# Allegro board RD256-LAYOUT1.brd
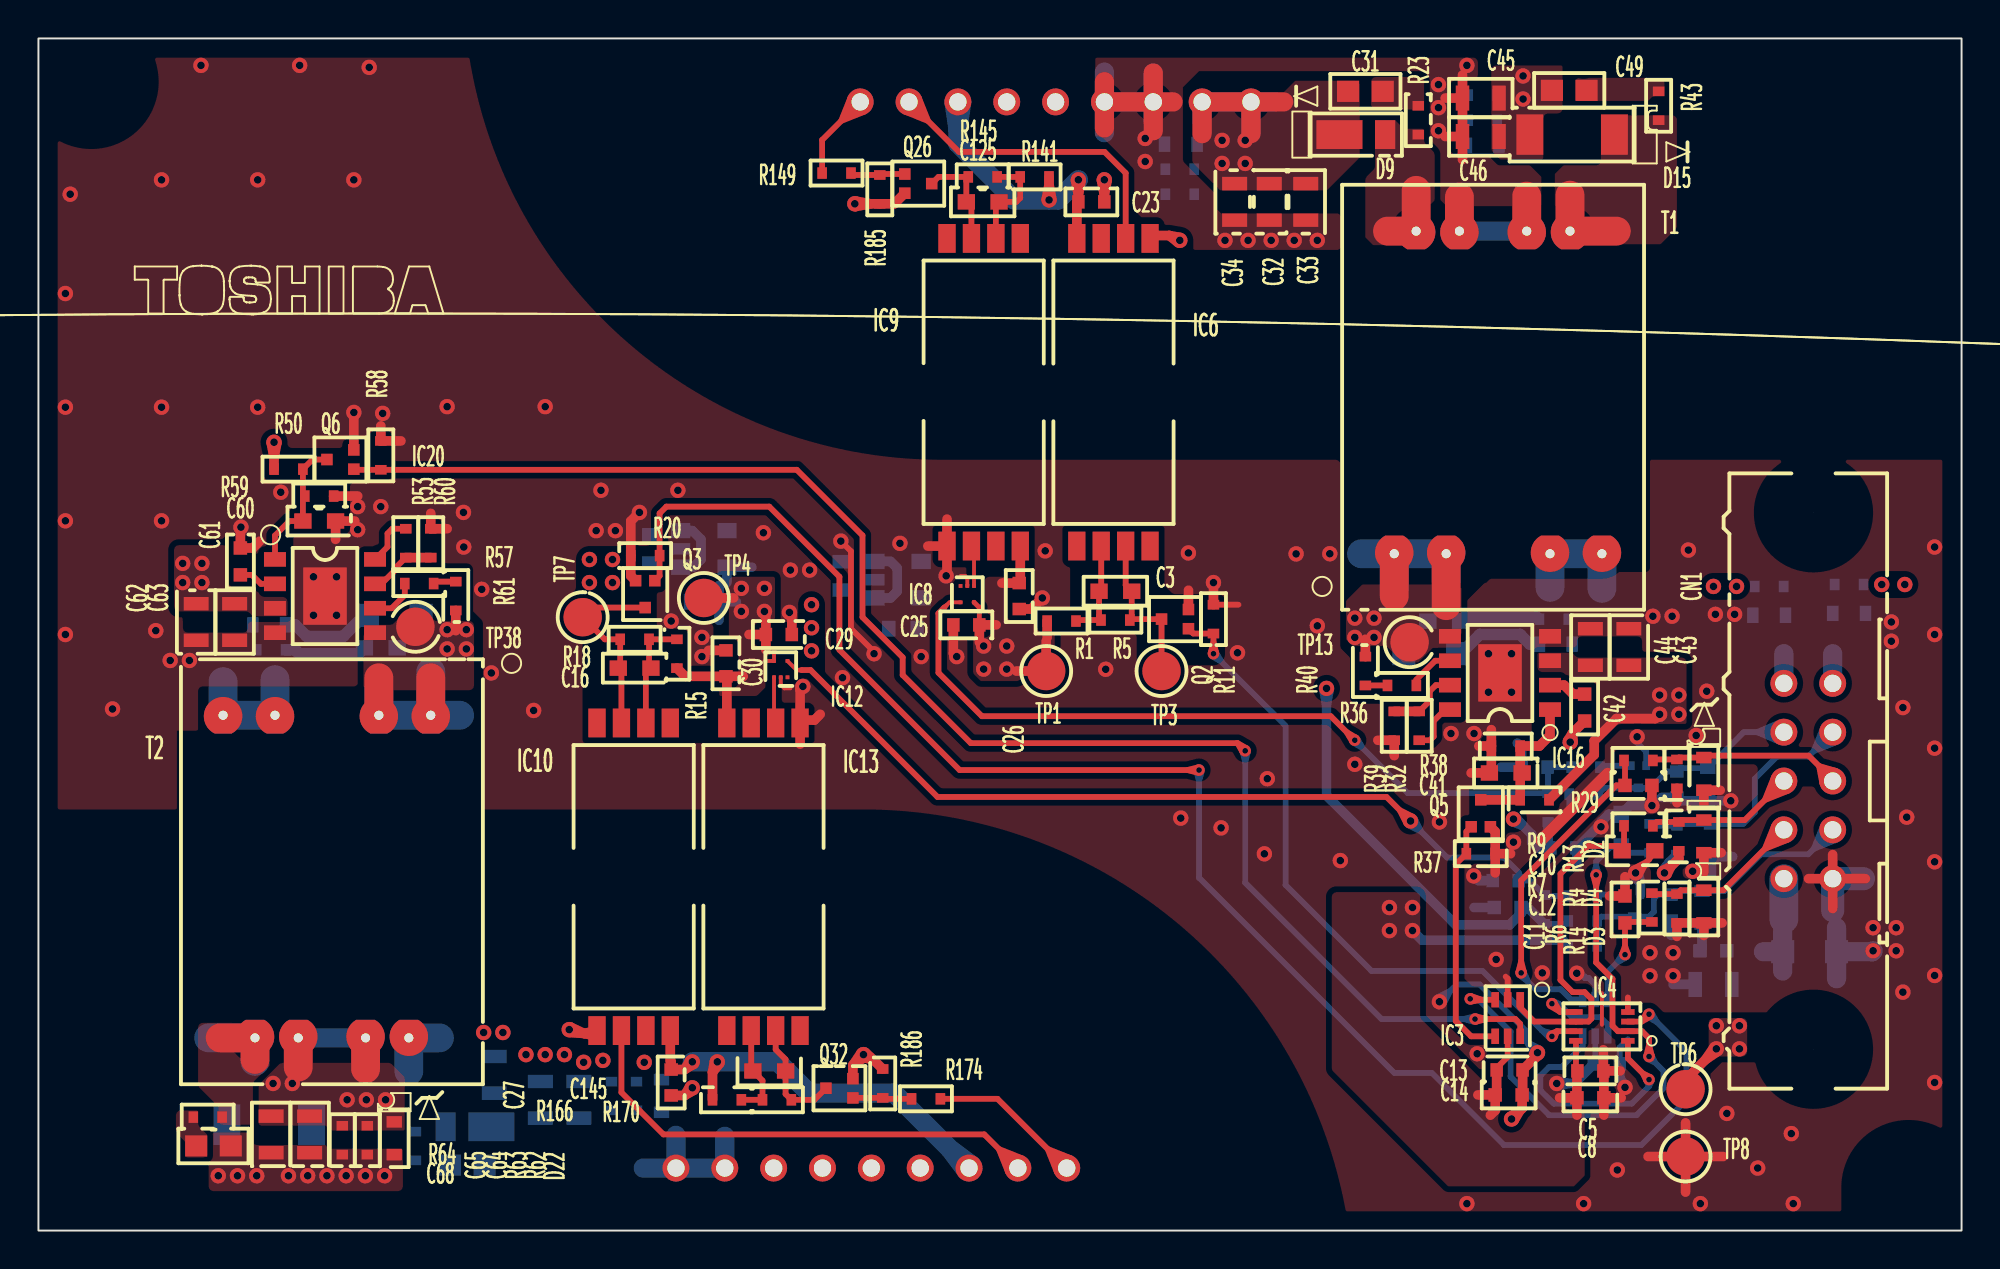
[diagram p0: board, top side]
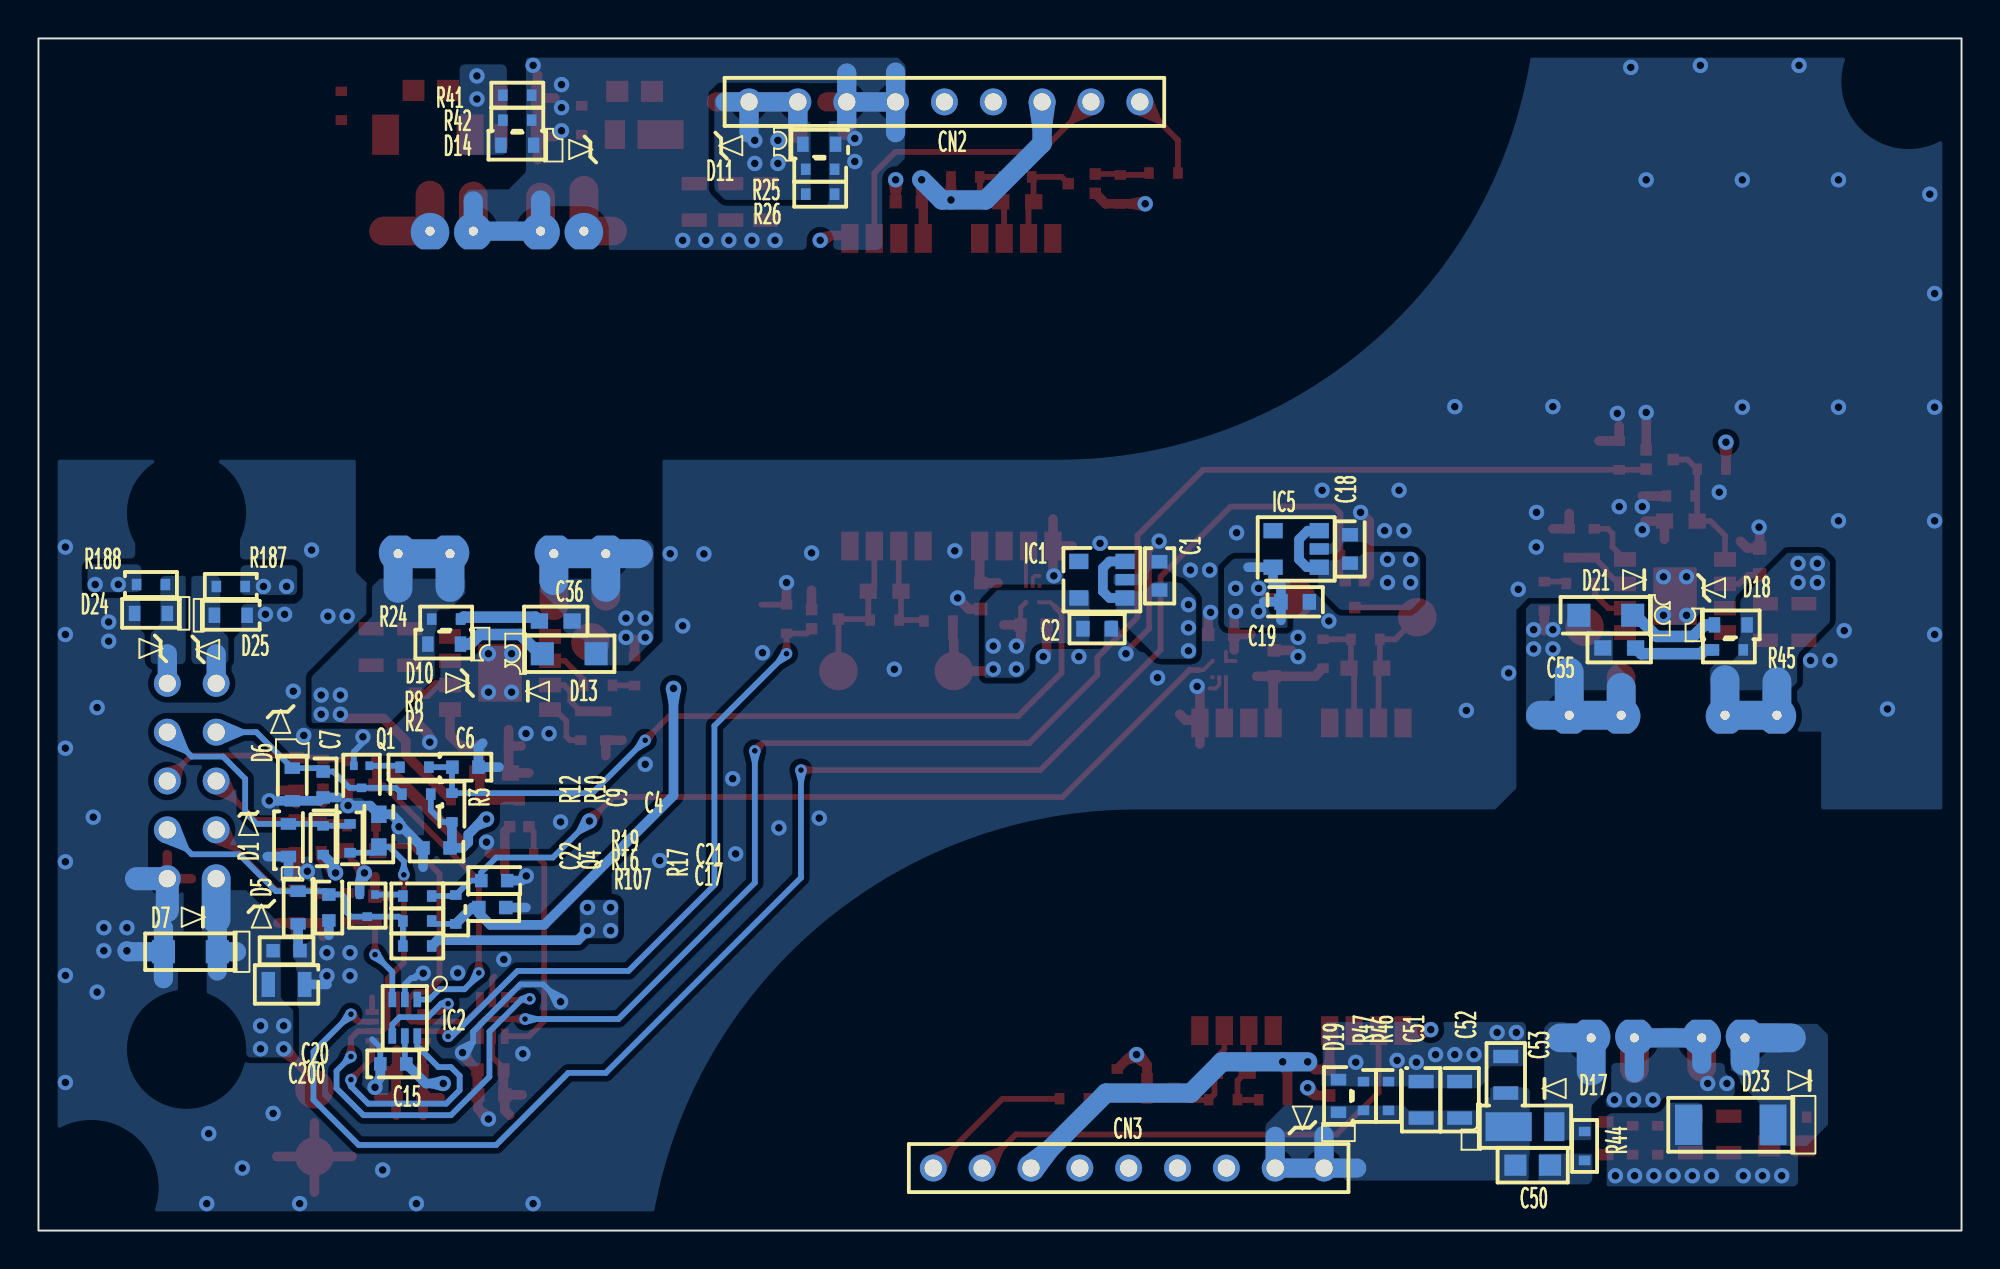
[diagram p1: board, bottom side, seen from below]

Outline 100 x 62 mm; copper layers: TOP, CONDUCTIVE2, CONDUCTIVE3, BOTTOM. Coordinates in mm from the lower left corner of the outline.
Outline path: rectangle 0,0 100,62

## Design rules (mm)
constraint set DEFAULT: 

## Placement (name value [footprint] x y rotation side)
C1  -  [C_CHP_TYYDN_L1_6W0_8H0_8A]  41.7 34.05 270 bottom
C2  -  [C_CHP_TYYDN_L1_6W0_8H0_8A]  44.95 31.3 0 bottom
C3  -  [C_CHP_YAGEO_L1_6W0_8H0_8]  56 33.25 180 top
C4  -  [C_CHP_TDK_L1_6W0_8H0_8]  79.3 19.9 180 bottom
C5  -  [C_CHP_MURATA_L1_6W0_8H0_8A]  80.7 8.3 180 top
C6  -  [C_CHP_MURATA_L1_6W0_8H0_8A]  77.8 24.1 0 bottom
C7  -  [C_CHP_MURATA_L1_6W0_8H0_8A]  85.2 23.2 90 bottom
C8  -  [C_CHP_TDK_L1_6W0_8H0_8]  80.7 6.9 180 top
C9  -  [C_CHP_YAGEO_L1_6W0_8H0_8]  82.3 20.8 270 bottom
C10  -  [C_CHP_TDK_L1_6W0_8H0_8]  83.2 23.15 180 top
C11  -  [C_CHP_TDK_L1_6W0_8H0_8]  82.5 16.7 270 top
C12  -  [C_CHP_YAGEO_L1_6W0_8H0_8]  83.2 19.75 180 top
C13  -  [C_CHP_MURATA_L1_6W0_8H0_8A]  76.5 8.35 180 top
C14  -  [C_CHP_TDK_L1_6W0_8H0_8]  76.45 7.05 180 top
C15  -  [C_CHP_MURATA_L1_6W0_8H0_8A]  81.55 8.67 180 bottom
C16  -  [C_CHP_YAGEO_L1_6W0_8H0_8]  31 29.25 0 top
C17  -  [C_CHP_TDK_L1_6W0_8H0_8]  76.4 16.8 0 bottom
C18  -  [C_CHP_TYYDN_L1_6W0_8H0_8A]  31.8 35.45 270 bottom
C19  -  [C_CHP_TYYDN_L1_6W0_8H0_8A]  34.65 32.7 0 bottom
C20  -  [C_CHP_TDK_L1_6W0_8H0_8]  87.1 14.55 0 bottom
C21  -  [C_CHP_MURATA_L1_6W0_8H0_8A]  76.3 18.2 0 bottom
C22  -  [C_CHP_MURATA_L1_6W0_8H0_8A]  84.9 16.8 90 bottom
C23  -  [C_CHP_MURATA_L1_6W0_8H0_8A]  54.75 53.5 180 top
C25  -  [C_CHP_MURATA_L1_6W0_8H0_8A]  48.25 31.5 0 top
C26  -  [C_CHP_MURATA_L1_6W0_8H0_8A]  51 33 90 top
C27  -  [C_CHP_MURATA_L1_6W0_8H0_8A]  32.9 7.7 90 top
C29  -  [C_CHP_MURATA_L1_6W0_8H0_8A]  38.5 31 180 top
C30  -  [C_CHP_MURATA_L1_6W0_8H0_8A]  35.75 29.5 270 top
C31  -  [C_CHP_KEMET_L1_6W0_8H0_8]  69 59.25 0 top
C32  -  [C_CHP_MURATA_L2_0W1_25H1_25]  64 53.5 90 top
C33  -  [C_CHP_MURATA_L2_0W1_25H1_25]  65.9 53.5 90 top
C34  -  [C_CHP_MURATA_L2_0W1_25H1_25]  62.2 53.5 90 top
C36  -  [C_CHP_YAGEO_L1_6W0_8H0_8]  73.1 31.7 0 bottom
C41  -  [C_CHP_YAGEO_L1_6W0_8H0_8]  76.3 23.8 0 top
C42  -  [C_CHP_TDK_L1_6W0_8H0_8]  80.4 27.2 90 top
C43  -  [C_CHP_MURATA_L2_0W1_25H1_25]  82.7 30.35 270 top
C44  -  [C_CHP_MURATA_L2_0W1_25H1_25]  80.7 30.35 270 top
C45  -  [C_CHP_MURATA_L2_0W1_25H1_25]  75 58.9 180 top
C46  -  [C_CHP_MURATA_L2_0W1_25H1_25]  75 56.9 180 top
C49  -  [C_CHP_KEMET_L1_6W0_8H0_8]  79.6 59.3 0 top
C50  -  [C_CHP_KEMET_L1_6W0_8H0_8]  22.3 3.4 180 bottom
C51  -  [C_CHP_MURATA_L2_0W1_25H1_25]  28.1 6.8 270 bottom
C52  -  [C_CHP_MURATA_L2_0W1_25H1_25]  26.1 6.8 270 bottom
C53  -  [C_CHP_MURATA_L2_0W1_25H1_25]  23.7 8.1 270 bottom
C55  -  [C_CHP_YAGEO_L1_6W0_8H0_8]  17.8 30.3 180 bottom
C60  -  [C_CHP_YAGEO_L1_6W0_8H0_8]  14.6 36.9 180 top
C61  -  [C_CHP_TDK_L1_6W0_8H0_8]  10.5 34.8 270 top
C62  -  [C_CHP_MURATA_L2_0W1_25H1_25]  8.2 31.65 90 top
C63  -  [C_CHP_MURATA_L2_0W1_25H1_25]  10.2 31.65 90 top
C64  -  [C_CHP_MURATA_L2_0W1_25H1_25]  14.1 5 90 top
C65  -  [C_CHP_MURATA_L2_0W1_25H1_25]  12.1 5 90 top
C68  -  [C_CHP_KEMET_L1_6W0_8H0_8]  9.1 4.4 180 top
C125  -  [C_CHP_YAGEO_L1_6W0_8H0_8]  49.1 53.5 0 top
C145  -  [C_CHP_YAGEO_L1_6W0_8H0_8]  38 8.3 180 top
C200  -  [C_CHP_MURATA_L2_0W1_25H1_25]  87.1 12.8 0 bottom
CN1  -  [CN_IMD_OMRON_XG4A_1031_M1_M2]  93.3 18.3 90 top
CN2  -  [OW_3_15_9P]  63.05 58.7 180 bottom
CN3  -  [OW_3_15_9P]  33.15 3.25 0 bottom
D1  -  [ZD_SMD_TSB_K_1_A_2_L1_2W0_8H0_6]  87 20.3 270 bottom
D2  -  [ZD_SMD_TSB_K_1_A_2_L1_2W0_8H0_6]  86.6 23.75 270 top
D3  -  [ZD_SMD_TSB_K_1_A_2_L1_2W0_8H0_6]  86.6 16.85 270 top
D4  -  [ZD_SMD_TSB_K_1_A_2_L1_2W0_8H0_6]  86.6 20.5 270 top
D5  -  [ZD_SMD_TSB_K_1_A_2_L1_2W0_8H0_6]  86.5 16.8 270 bottom
D6  -  [ZD_SMD_TSB_K_1_A_2_L1_2W0_8H0_6]  86.8 23.2 270 bottom
D7  -  [D_SMD_TSB_K_2_A_1_L2_6W1_6H0_98]  92.1 14.5 0 bottom
D9  -  [D_SMD_DIODES_K_C_A_A_L2_8W1_78H0_98]  68.5 57 0 top
D10  -  [ZD_SMD_TSB_K_1_A_2_L1_2W0_8H0_6]  78.9 30.5 0 bottom
D11  -  [ZD_SMD_TSB_K_1_A_2_L1_2W0_8H0_6]  59.4 56.5 180 bottom
D13  -  [D_SMD_TSB_K_2_A_1_L2_6W1_6H0_98]  72.4 30 180 bottom
D14  -  [ZD_SMD_TSB_K_1_A_2_L1_2W0_8H0_6]  75.1 56.45 0 bottom
D15  -  [D_SMD_TSB_K_2_A_1_L3_8W2_4H0_98]  79.75 57 180 top
D17  -  [D_SMD_DIODES_K_C_A_A_L2_8W1_78H0_98]  22.7 5.4 180 bottom
D18  -  [ZD_SMD_TSB_K_1_A_2_L1_2W0_8H0_6]  12 31.5 180 bottom
D19  -  [ZD_SMD_TSB_K_1_A_2_L1_2W0_8H0_6]  32.4 7 90 bottom
D21  -  [D_SMD_TSB_K_2_A_1_L2_6W1_6H0_98]  18.5 32 0 bottom
D22  -  [ZD_SMD_TSB_K_1_A_2_L1_2W0_8H0_6]  18.5 4.8 270 top
D23  -  [D_SMD_TSB_K_2_A_1_L3_8W2_4H0_98]  12 5.5 0 bottom
D24  -  [ZD_SMD_TSB_K_1_A_2_L1_2W0_8H0_6]  94.15 32.1 0 bottom
D25  -  [ZD_SMD_TSB_K_1_A_2_L1_2W0_8H0_6]  90 32 180 bottom
IC1  -  [IC_SC74A_TSB_L2_9W1_6H1_15_RP0_05]  44.7 33.85 90 bottom
IC2  -  [IC_SOP_6_TSB_L2_0W1_25H0_95_RP0_05]  80.95 11.07 0 bottom
IC3  -  [IC_SOP_6_TSB_L2_0W1_25H0_95_RP0_05]  76.4 11.05 180 top
IC4  -  [IC_SOP_8_TSB_L2_0W2_3H0_75_P0_5_RP0_05]  81.3 10.62 90 top
IC5  -  [IC_SC74A_TSB_L2_9W1_6H1_15_RP0_05]  34.6 35.45 90 bottom
IC6  -  [PC_SOP_8_TSB_L6_25W13_75H3_7_P1_27_3]  55.9 43.6 0 top
IC8  -  [IC_SMD_5_TSB_L1_0W0_8H0_48_RCNT]  48.3 33.1 180 top
IC9  -  [PC_SOP_8_TSB_L6_25W13_75H3_7_P1_27_3]  49.15 43.6 180 top
IC10  -  [PC_SOP_8_TSB_L6_25W13_75H3_7_P1_27_3]  30.95 18.4 180 top
IC12  -  [IC_SMD_5_TSB_L1_0W0_8H0_48_RCNT]  38.6 29.2 0 top
IC13  -  [PC_SOP_8_TSB_L6_25W13_75H3_7_P1_27_3]  37.7 18.4 0 top
IC16  -  [IC_SOP_8S1_AD_L5_004W3_988H1_752_P1_27_2]  76 29 90 top
IC20  -  [IC_SOP_8S1_AD_L5_004W3_988H1_752_P1_27_2]  14.9 33 270 top
NOREF  -  []  5 47.7 0 top
Q1  -  [TR_SMD_3_TSB_B_1_E_2_C_3_L1_2W0_8H0_5]  83.2 23.6 0 bottom
Q2  -  [FET_SMD_TSB_G_1_S_2_D_3_L1_6W0_8H0_75]  59.1 31.8 90 top
Q3  -  [FET_SMD_TSB_G_1_S_2_D_3_L1_6W0_8H0_75]  31.55 33.1 180 top
Q4  -  [TR_SMD_3_TSB_B_1_E_2_C_3_L1_2W0_8H0_5]  82.9 16.9 0 bottom
Q5  -  [FET_SMD_TSB_G_1_S_2_D_3_L1_6W0_8H0_75]  75 21.7 0 top
Q6  -  [FET_SMD_TSB_G_1_S_2_D_3_L1_6W0_8H0_75]  15.7 40.1 90 top
Q26  -  [FET_SMD_TSB_G_1_S_2_D_3_L1_6W0_8H0_75]  45.75 54.45 270 top
Q32  -  [FET_SMD_TSB_G_1_S_2_D_3_L1_6W0_8H0_75]  41.65 7.4 90 top
R1  -  [R_CHP_KOA_L1_6W0_8H0_45]  53.2 31.7 180 top
R2  -  [R_CHP_KOA_L1_6W0_8H0_45]  80.35 22.7 180 bottom
R3  -  [R_CHP_KOA_L1_6W0_8H0_45]  78.5 22 270 bottom
R4  -  [R_CHP_KOA_L1_6W0_8H0_45]  85.3 20.5 270 top
R5  -  [R_CHP_KOA_L1_6W0_8H0_45]  56 31.75 180 top
R6  -  [R_CHP_KOA_L1_6W0_8H0_45]  83.9 16.8 270 top
R7  -  [R_CHP_KOA_L1_6W0_8H0_45]  83.2 21.05 180 top
R8  -  [R_CHP_KOA_L1_6W0_8H0_45]  80.45 24.1 180 bottom
R9  -  [R_CHP_KOA_L1_6W0_8H0_45]  83.2 24.45 180 top
R10  -  [R_CHP_KOA_L1_6W0_8H0_45]  83.8 20.4 270 bottom
R11  -  [R_CHP_KOA_L1_6W0_8H0_45]  61.1 31.8 270 top
R12  -  [R_CHP_KOA_L1_6W0_8H0_45]  85.2 20.3 270 bottom
R13  -  [R_CHP_KOA_L1_6W0_8H0_45]  85.2 23.75 90 top
R14  -  [R_CHP_KOA_L1_6W0_8H0_45]  85.2 16.75 90 top
R15  -  [R_CHP_KOA_L1_6W0_8H0_45]  33.2 30 270 top
R16  -  [R_CHP_KOA_L1_6W0_8H0_45]  80.3 16.1 180 bottom
R17  -  [R_CHP_KOA_L1_6W0_8H0_45]  78.3 16.7 270 bottom
R18  -  [R_CHP_KOA_L1_6W0_8H0_45]  31 30.75 0 top
R19  -  [R_CHP_KOA_L1_6W0_8H0_45]  80.3 17.4 180 bottom
R20  -  [R_CHP_KOA_L1_6W0_8H0_45]  31.55 35.1 0 top
R23  -  [R_CHP_KOA_L1_6W0_8H0_45]  71.75 57.75 270 top
R24  -  [R_CHP_KOA_L1_6W0_8H0_45]  78.8 31.8 0 bottom
R25  -  [R_CHP_KOA_L1_6W0_8H0_45]  59.35 55.2 0 bottom
R26  -  [R_CHP_KOA_L1_6W0_8H0_45]  59.35 53.9 0 bottom
R29  -  [R_CHP_KOA_L1_6W0_8H0_45]  77.8 22.4 0 top
R32  -  [R_CHP_KOA_L1_6W0_8H0_45]  71.8 26.25 270 top
R36  -  [R_CHP_KOA_L1_6W0_8H0_45]  70.9 28.35 0 top
R37  -  [R_CHP_KOA_L1_6W0_8H0_45]  75 19.6 180 top
R38  -  [R_CHP_KOA_L1_6W0_8H0_45]  76.3 25.2 0 top
R39  -  [R_CHP_KOA_L1_6W0_8H0_45]  70.5 26.25 90 top
R40  -  [R_CHP_KOA_L1_6W0_8H0_45]  69 29.1 270 top
R41  -  [R_CHP_KOA_L1_6W0_8H0_45]  75.1 59.05 180 bottom
R42  -  [R_CHP_KOA_L1_6W0_8H0_45]  75.1 57.75 180 bottom
R43  -  [R_CHP_KOA_L1_6W0_8H0_45]  84.25 58.5 270 top
R44  -  [R_CHP_KOA_L1_6W0_8H0_45]  19.6 4.4 90 bottom
R45  -  [R_CHP_KOA_L1_6W0_8H0_45]  12.1 30.2 180 bottom
R46  -  [R_CHP_KOA_L1_6W0_8H0_45]  29.8 7 270 bottom
R47  -  [R_CHP_KOA_L1_6W0_8H0_45]  31.1 7 270 bottom
R50  -  [R_CHP_KOA_L1_6W0_8H0_45]  13 39.6 180 top
R53  -  [R_CHP_KOA_L1_6W0_8H0_45]  19.1 35.75 90 top
R57  -  [R_CHP_KOA_L1_6W0_8H0_45]  19.8 33.65 180 top
R58  -  [R_CHP_KOA_L1_6W0_8H0_45]  17.8 40.32 270 top
R59  -  [R_CHP_KOA_L1_6W0_8H0_45]  14.6 38.2 180 top
R60  -  [R_CHP_KOA_L1_6W0_8H0_45]  20.4 35.75 270 top
R61  -  [R_CHP_KOA_L1_6W0_8H0_45]  21.7 33 90 top
R62  -  [R_CHP_KOA_L1_6W0_8H0_45]  17.1 4.7 90 top
R63  -  [R_CHP_KOA_L1_6W0_8H0_45]  15.8 4.7 90 top
R64  -  [R_CHP_KOA_L1_6W0_8H0_45]  8.8 5.9 0 top
R107  -  [R_CHP_KOA_L1_6W0_8H0_45]  80.3 14.8 180 bottom
R141  -  [R_CHP_KOA_L1_6W0_8H0_45]  51.8 54.8 0 top
R145  -  [R_CHP_KOA_L1_6W0_8H0_45]  49.1 54.8 0 top
R149  -  [R_CHP_KOA_L1_6W0_8H0_45]  41.5 55 0 top
R166  -  [R_CHP_KOA_L1_6W0_8H0_45]  35.8 6.8 180 top
R170  -  [R_CHP_KOA_L1_6W0_8H0_45]  38.4 6.8 180 top
R174  -  [R_CHP_KOA_L1_6W0_8H0_45]  46.15 6.85 180 top
R185  -  [R_CHP_KOA_L1_6W0_8H0_45]  43.75 54.15 90 top
R186  -  [R_CHP_KOA_L1_6W0_8H0_45]  43.9 7.65 270 top
R187  -  [R_CHP_KOA_L1_6W0_8H0_45]  90 33.5 180 bottom
R188  -  [R_CHP_KOA_L1_6W0_8H0_45]  94.15 33.6 180 bottom
T1  -  [750345989_2]  70.5 35.2 90 top
T2  -  [750345989_2]  20.4 26.8 270 top
TP1  -  [TPAD_P_C2_0_RP0_05_MN]  52.4 29.1 90 top
TP3  -  [TPAD_P_C2_0_RP0_05_MN]  58.4 29.1 270 top
TP4  -  [TPAD_P_C2_0_RP0_05_MN]  34.6 32.9 0 top
TP6  -  [TPAD_P_C2_0_RP0_05_MN]  85.65 7.35 90 top
TP7  -  [TPAD_P_C2_0_RP0_05_MN]  28.3 31.9 90 top
TP8  -  [TPAD_P_C2_0_RP0_05_MN]  85.65 3.85 0 top
TP13  -  [TPAD_P_C2_0_RP0_05_MN]  71.3 30.6 0 top
TP38  -  [TPAD_P_C2_0_RP0_05_MN]  19.6 31.4 180 top

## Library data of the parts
C1 C2 C18 C19 = MSASU168SB7474KTNB25
C3 C9 C12 C16 C36 C41 C55 C60 C125 C145 = CC0603KRX7R9BB471
C4 C17 = CGA3E3X7R1H334K080AB
C5 C13 C15 C23 C25-C27 C29 C30 = GCJ188R71H104KA12D
C6 C7 C21 C22 = GCM188R71H102KA37D
C8 C14 C20 C42 C61 = C1608X5R1H105K080DB
C10 C11 = C1608X5R1H224K080AB
C31 C49 C50 C68 = C0603C470K1RACTU
C32-C34 C45 C46 C51-C53 C64 C65 C200 = GRM21BR61H106KE43L
C43 C44 C62 C63 = GRM21BZ71H475KE15L
CN1 = XG4A-1031_M1_M2: alternate symbols: (CN1_CN_IMD_OMRON_XG4A_1031_M1_M2)
CN2 CN3 = OW-3-15-9P: alternate symbols: (T:OW_3_15_9P;B:OW_3_15_9P,CN2_OW_3_15_9P,CN3_OW_3_15_9P)
D1-D6 D24 D25 = CEZ6V8,L3F
D7 = CRZ36(TE85L,Q,M)
D9 D17 = DFLS1100-7_Pin(K_C.A_A)
D10 D18 = CEZ24V,L3F
D11 D19 = CEZ30V,L3F
D13 D21 = CRS13
D14 D22 = CEZ8V2,L3F
D15 D23 = CMS03(T2L,TEMQ)
IC1 IC5 = TCR1HF50B,LM(CT: alternate symbols: (T:IC_SC74A_TSB_L2_9W1_6H1_15_rp0_05;B:IC_SC74A_TSB_L2_9W1_6H1_15_rp0_05,IC5_IC_SC74A_TSB_L2_9W1_6H1_15_rp0)
IC2 = TC7PZ17FU,LJ(CT
IC3 = TC7PZ14FU,LJ(CT
IC4 = TC7WZ08FK,LJ(CT
IC6 IC9 IC10 IC13 = TLP2861L
IC8 IC12 = TC7SZ04AFS,L3J
IC16 IC20 = LT8302IS8E#TRPBF
Q1 Q4 = 2SC5658T2LR
Q2 Q3 Q5 Q6 Q26 Q32 = SSM3K15AFS,LF(T
R1 R15 = RK73H1JTTD5600F
R2 R4 R12-R14 R16 R107 = RK73H1JTTD4701F
R3 R11 R17 R20 R37 R39 R58 R60 = RK73H1JTTD1002F
R5-R7 R9 R10 R18 = RK73H1JTTD1001F
R8 R19 = RK73H1JTTD4702F
R23 R43 R44 R64 = RK73H1JTTD33R0F
R24 R45 = RK73H1JTTD39R0F
R25 R26 R41 R42 R46 R47 R62 R63 = RK73H1JTTD3001F
R29 R50 = RK73H1JTTD2403F
R32 R53 = RK73H1JTTD3903F
R36 R57 = RK73H1JTTD1003F
R38 R59 = RK73H1JTTD2202F
R40 R61 = RK73H1JTTD1602F
R141 R166 = RK73B1JTTD561J
R145 R149 R170 R174 = RK73B1JTTD102J
R185 R186 = RK73B1JTTD104J
R187 R188 = RK73Z1JTTD
T1 T2 = 750345989: alternate symbols: (750345989_3)
TP1 TP3 TP4 TP6-TP8 TP13 TP38 = TPAD-P_C2.0-RP0.05-MN

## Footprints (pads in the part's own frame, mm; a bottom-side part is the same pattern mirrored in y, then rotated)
750345989_2
  custom 0.475x0.475 hole 1.2: 1(0,0) 2(0,-2.7) 4(0,-8.1) 5(0,-10.8)
  custom 0.47x0.47 hole 1.2: 12(16.78,-9.14) 13(16.78,-6.89) 14(16.78,-3.39) 15(16.78,-1.14)
C_CHP_KEMET_L1_6W0_8H0_8
  rect 1.15x1.1 smd: 1(-0.9,0) 2(0.9,0)
C_CHP_MURATA_L1_6W0_8H0_8A
  rect 0.65x0.7 smd: 1(-0.675,0) 2(0.675,0)
C_CHP_MURATA_L2_0W1_25H1_25
  rect 0.7x1.3 smd: 1(-0.95,0) 2(0.95,0)
C_CHP_TDK_L1_6W0_8H0_8
  rect 0.7x0.7 smd: 1(-0.7,0) 2(0.7,0)
C_CHP_TYYDN_L1_6W0_8H0_8A
  rect 0.7x0.825 smd: 1(-0.738,0) 2(0.738,0)
C_CHP_YAGEO_L1_6W0_8H0_8
  rect 0.9x0.8 smd: 1(-0.85,0) 2(0.85,0)
CN_IMD_OMRON_XG4A_1031_M1_M2
  round 0.01 hole 3.2 unplated: (-8.87,1) (19.03,1)
  round 1.4 hole 0.9: 1(0,0) 2(0,2.54) 3(2.54,0) 4(2.54,2.54) 5(5.08,0) 6(5.08,2.54) 7(7.62,0) 8(7.62,2.54) 9(10.16,0) 10(10.16,2.54)
D_SMD_DIODES_K_C_A_A_L2_8W1_78H0_98
  rect 1.05x1.5 smd: A(1.525,0)
  rect 2.4x1.5 smd: C(-0.85,0)
D_SMD_TSB_K_2_A_1_L2_6W1_6H0_98
  rect 1.2x1.2 smd: 1(1.4,0) 2(-1.4,0)
D_SMD_TSB_K_2_A_1_L3_8W2_4H0_98
  rect 1.4x2.1 smd: 1(2.2,0) 2(-2.2,0)
FET_SMD_TSB_G_1_S_2_D_3_L1_6W0_8H0_75
  rect 0.6x0.6 smd: 1(-0.5,-0.7) 2(0.5,-0.7) 3(0,0.7)
IC_SC74A_TSB_L2_9W1_6H1_15_RP0_05
  rect 0.8x1 smd: 1(-0.95,-1.2) 3(0.95,-1.2) 4(0.95,1.2) 5(-0.95,1.2)
  rect 0.6x1 smd: 2(0,-1.2)
IC_SMD_5_TSB_L1_0W0_8H0_48_RCNT
  rect 0.2x0.2 smd: 1(-0.35,-0.425) 2(0,-0.425) 3(0.35,-0.425) 4(0.35,0.425) 5(-0.35,0.425)
IC_SOP_6_TSB_L2_0W1_25H0_95_RP0_05
  rect 0.4x0.8 smd: 1(-0.65,-0.95) 2(0,-0.95) 3(0.65,-0.95) 4(0.65,0.95) 5(0,0.95) 6(-0.65,0.95)
IC_SOP_8_TSB_L2_0W2_3H0_75_P0_5_RP0_05
  rect 0.3x0.7 smd: 1(-0.75,-1.35) 2(-0.25,-1.35) 3(0.25,-1.35) 4(0.75,-1.35) 5(0.75,1.35) 6(0.25,1.35) 7(-0.25,1.35) 8(-0.75,1.35)
IC_SOP_8S1_AD_L5_004W3_988H1_752_P1_27_2
  rect 0.762x1.143 smd: 1(-1.905,-2.602) 2(-0.635,-2.602) 3(0.635,-2.602) 4(1.905,-2.602) 5(1.905,2.602) 6(0.635,2.602) 7(-0.635,2.602) 8(-1.905,2.602)
  rect 2.99x2.26 smd: 9(0,0)
OW_3_15_9P
  round 1.4 hole 0.9: 1(0,0) 2(2.54,0) 3(5.08,0) 4(7.62,0) 5(10.16,0) 6(12.7,0) 7(15.24,0) 8(17.78,0) 9(20.32,0)
PC_SOP_8_TSB_L6_25W13_75H3_7_P1_27_3
  rect 0.9x1.5 smd: 1(-1.905,-8) 2(-0.635,-8) 3(0.635,-8) 4(1.905,-8) 5(1.905,8) 6(0.635,8) 7(-0.635,8) 8(-1.905,8)
R_CHP_KOA_L1_6W0_8H0_45
  rect 0.5x0.6 smd: 1(-0.75,0) 2(0.75,0)
TPAD_P_C2_0_RP0_05_MN
  round 2 smd: 1(0,0)
TR_SMD_3_TSB_B_1_E_2_C_3_L1_2W0_8H0_5
  rect 0.4x0.45 smd: 1(-0.4,-0.575) 2(0.4,-0.575)
  rect 0.5x0.45 smd: 3(0,0.575)
ZD_SMD_TSB_K_1_A_2_L1_2W0_8H0_6
  rect 0.6x0.8 smd: 1(-0.85,0) 2(0.85,0)

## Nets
5V_A: C2.2 C4.2 C5.2 C8.2 C13.2 C14.2 C15.2 C25.2 C26.2 IC1.5 IC2.5 IC3.5 IC4.8 IC8.5 IC9.8 R1.2 R2.2 R3.2 R4.2 R12.2 R107.2 R188.1 TP1.1
5V_B: C17.2 C19.2 C29.2 C30.2 IC5.5 IC12.5 IC13.8 R15.2 R16.2 R17.2 R187.2 TP4.1
GND: C1.1 C2.1 C4.1 C5.1 C6.1 C7.1 C8.1 C9.1 C10.1 C11.1 C12.1 C13.1 C14.1 C15.1 C17.1 C18.1 C19.1 C20.1 C21.1 C22.1 C25.1 C26.1 C29.1 C30.1 C41.1 C42.1 C43.1 C44.1 C60.1 C61.1 C62.1 C63.1 C200.1 CN1.1 D1.2 D2.2 D3.2 D4.2 D5.2 D6.2 D7.1 D24.2 D25.2 IC1.2 IC2.2 IC3.2 IC4.4 IC5.2 IC8.2 IC9.5 IC12.2 IC13.5 IC16.4 IC16.9 IC20.4 IC20.9 Q1.2 Q2.2 Q3.2 Q4.2 Q5.2 Q6.2 R11.1 R13.1 R14.1 R20.1 R37.1 R38.1 R39.1 R58.1 R59.1 R60.1 TP8.1
VDD: C1.2 C18.2 C20.2 C43.2 C44.2 C62.2 C63.2 C200.2 CN1.2 D7.2 D10.2 D18.2 IC1.1 IC1.3 IC5.1 IC5.3 IC16.3 IC20.3 R24.2 R29.2 R45.2 R50.2 T1.4 T1.5 T2.4 T2.5 TP6.1
VEE_A: C23.1 C45.1 C46.1 C49.1 CN2.5 CN2.6 D14.2 D15.1 IC6.5 Q26.2 R41.1 R42.1 R185.1
VEE_B: C27.1 C64.1 C65.1 C68.1 CN3.5 CN3.6 D22.2 D23.1 IC10.5 Q32.2 R62.1 R63.1 R186.1
A_ENA: CN1.7 D1.1 R10.1 R12.1
A_FLT: C7.2 CN1.8 D6.1 Q1.3 R2.1
A_INA: CN1.5 D2.1 R9.1 R13.2
ANODE_A: C3.2 IC6.2 R1.1 R5.2
ANODE_B: C16.2 IC10.2 R15.1 R18.2
B_ENA: CN1.6 D4.1 R4.1 R7.1
B_FLT: C22.2 CN1.3 D5.1 Q4.3 R16.1 R107.1
B_INA: CN1.4 D3.1 R6.1 R14.2
CATHODE_A: C3.1 IC6.3 Q2.3 R5.1 TP3.1
CATHODE_B: C16.1 IC10.3 Q3.3 R18.1 TP7.1
FAULT_2_A: CN2.9 R149.1
FAULT_2_B: CN3.9 R174.1
FAULT_A: C6.2 IC8.4 R3.1 R8.2
FAULT_B: C21.2 IC12.4 R17.1 R19.2
FYB_DISABLE_A: IC3.4 Q5.1 R37.2
FYB_DISABLE_B: IC3.6 Q6.1 R58.2
IN2_N_A: CN2.8 IC6.6
IN2_N_B: CN3.8 IC10.6
SIG00001: IC1.4
SIG00002: IC5.4
SIG00005: Q1.1 R8.1
SIG00006: C9.2 IC3.3 IC4.2 R10.2
SIG00008: C11.2 IC2.3 R6.2
SIG00010: IC4.7 Q2.1 R11.2
SIG00011: IC4.3 Q3.1 R20.2
SIG00012: Q4.1 R19.1
SIG00015: CN1.9 D24.1 R188.2
SIG00017: CN1.10 D25.1 R187.1
SIG00018: IC6.1
SIG00019: IC6.7
SIG00020: IC6.4
SIG00023: IC9.1
SIG00024: IC9.7
SIG00025: IC9.4
SIG00026: IC8.1 IC9.6
SIG00027: IC8.3
SIG00028: IC10.1
SIG00029: IC10.7
SIG00030: IC10.4
SIG00033: IC13.1
SIG00034: IC13.7
SIG00035: IC13.4
SIG00036: IC12.1 IC13.6
SIG00037: IC12.3
SIG00040: D10.1 D13.2
SIG00041: C36.2 R24.1
SIG00042: D9.A R23.2 T1.15
SIG00043: C31.2 R23.1
SIG00044: C31.1 C32.2 C33.2 C34.2 CN2.1 CN2.2 D9.C D11.1 R25.2 R26.2
SIG00050: D15.2 R43.2 T1.12
SIG00051: C49.2 R43.1
SIG00052: C41.2 IC16.1 Q5.3 R29.1 R38.2
SIG00053: C42.2 IC16.2
SIG00054: IC16.8 R32.2
SIG00055: IC16.6 R36.2
SIG00056: R36.1 R40.2
SIG00057: C36.1 D13.1 IC16.5 R40.1 T1.1 T1.2 TP13.1
SIG00057_502750: C55.1 D21.1 IC20.5 R61.1 T2.1 T2.2 TP38.1
SIG00058: IC16.7 R32.1 R39.2
SIG00061: D18.1 D21.2
SIG00062: C55.2 R45.1
SIG00063: D17.A R44.2 T2.15
SIG00064: C50.2 R44.1
SIG00065: C50.1 C51.2 C52.2 C53.2 CN3.1 CN3.2 D17.C D19.1 R46.2 R47.2
SIG00071: D23.2 R64.2 T2.12
SIG00072: C68.2 R64.1
SIG00073: C60.2 IC20.1 Q6.3 R50.1 R59.2
SIG00074: C61.2 IC20.2
SIG00075: IC20.8 R53.2
SIG00076: IC20.6 R57.2
SIG00077: R57.1 R61.2
SIG00079: IC20.7 R53.1 R60.2
SIG00190: Q26.1 R149.2 R185.2
SIG00227: Q32.1 R174.2 R186.2
SIG00236: C12.2 IC3.1 IC4.6 R7.2
SIG00237: C10.2 IC2.1 R9.2
SIG00238: IC2.4 IC4.5
SIG00239: IC2.6 IC4.1
VE_A: C32.1 C33.1 C34.1 C45.2 C46.2 CN2.3 CN2.4 D11.2 D14.1 R25.1 R26.1 R41.2 R42.2 T1.13 T1.14
VE_B: C51.1 C52.1 C53.1 C64.2 C65.2 CN3.3 CN3.4 D19.2 D22.1 R46.1 R47.1 R62.2 R63.2 T2.13 T2.14
VL_A: C23.2 CN2.7 IC6.8 R141.2
VL_B: C27.2 CN3.7 IC10.8 R166.2
N02405: C125.2 IC9.2 R141.1 R145.2
N76786: C125.1 IC9.3 Q26.3 R145.1
N938622: C145.2 IC13.2 R166.1 R170.2
N938626: C145.1 IC13.3 Q32.3 R170.1

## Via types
v1: diameter 0.8, hole 0.4, TOP to BOTTOM, 227 vias
v2: diameter 0.6, hole 0.3, TOP to BOTTOM, 14 vias

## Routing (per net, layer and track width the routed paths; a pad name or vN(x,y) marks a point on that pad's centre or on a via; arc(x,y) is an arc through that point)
5V_A: length 58.6
  TOP w0.25: C25.2 48.92,32.4 48.65,32.67
  TOP w0.3: IC4.8 79.95,8.38 C5.2 ; C13.2 75.83,8.45 76.4,9.03 IC3.5
  TOP w0.5: 75.5,6 75.75,6.25 C14.2 ; R1.2 52.45,30.85 ; C13.2 75.83,7.13 C14.2 ; 52.4,30.65 TP1.1 50.85,29.1 ; C8.2 80,6 ; C8.2 79.1,6.9 ; C8.2 80,8.28 C5.2 ; C14.2 74.85,7.05 ; 50.1,33.67 C26.2 51.05,33.73 51.05,35.45 ; v1(84.55,18.6) 85.3,19.35 R4.2 ; 48.92,30.6 C25.2 49.8,31.5
  CONDUCTIVE3 w1: 81.6,28.6 83.55,30.55 92.8,30.55 v1(95.85,33.6) v1(97.05,33.6)
  BOTTOM w0.3: C15.2 80.95,8.74 IC2.5 ; R3.2 79,21.25 79.6,21.85 R2.2
  BOTTOM w0.5: v1(71.45,15.6) 71.95,15.1 79.25,15.1 R107.2 ; R12.2 84.8,19.15 v1(84.55,18.6) ; v1(78.95,7.65) 79.86,7.65 C15.2 ; R3.2 78.5,20 C4.2 77.94,19.9 77.65,20.19 77.65,20.6 77.19,21.06 v1(76.7,21.4)
  vias: v1(49.15,30.4) v1(49.15,29.2) v1(50.35,30.4) v1(50.35,29.2) v1(70.25,16.8) v1(70.25,15.6) v1(71.45,16.8)
5V_B: length 61.2
  TOP w0.2: 37.75,29.62 IC12.5 38.25,30.1
  TOP w0.5: C29.2 37.83,31.9 ; C29.2 36.95,31 ; C29.2 37.83,30.2 ; R15.2 33.62,28.82 C30.2 ; C30.2 36.65,28.82 ; C30.2 35.8,28.78 35.8,26.55 ; TP4.1 36.15,32.9
  CONDUCTIVE3 w0.8: v1(88.3,33.5) v1(87.1,33.5) 86.95,33.35 83.5,33.35 79.55,29.4 79.55,27.25 76.95,24.65
  CONDUCTIVE3 w1: 65.8,29.4 64.4,30.8 64.4,31.1 63.35,32.15 ; 71.15,26.8 67.7,26.8
  BOTTOM w0.3: R17.2 79.4,15.95 R16.2
  BOTTOM w0.5: C19.2 35.39,33.55 ; C19.2 35.39,31.74 ; C19.2 36.29,32.7 ; 37.1,34.5 IC5.5 35.8,33.7 ; R17.2 77.45,16.8 C17.2 77.1,16.5 76.5,15.9 73.7,15.9 66.98,22.62 v1(66.98,28.2)
  vias: v1(36.55,33.4) v1(36.55,32.2) v1(37.75,33.4) v1(37.75,32.2)
GND: length 137.8
  TOP w0.2: 81.3,12.35 81.3,10.7 ; IC8.2 48.3,33.94 48.19,34.05 47.95,34.05 ; IC12.2 38.6,28.39 38.79,28.2 39.1,28.2
  TOP w0.3: v1(43.45,30) 43.45,30.1 42.25,31.3 42.25,35.33 v1(41.72,35.86) ; IC3.2 76.4,13.1 76.3,13.2 ; v1(83.05,18.6) 83.75,19.3 C12.1 ; R11.1 62.4,32.55 ; 82.65,12.12 IC4.4
  TOP w0.5: IC9.5 47.24,37 ; IC9.5 47.24,34.09 v1(47.2,34.05) ; IC9.5 46.25,35.6 ; Q2.2 59.8,33.3 ; C8.1 81.4,8.28 C5.1 ; C8.1 82.3,6.9 ; C8.1 81.4,6 ; TP8.1 87.6,3.85 ; TP8.1 85.65,5.6 ; TP8.1 85.65,2 ; TP8.1 83.7,3.85 ; 17.8,41.85 R58.1 18.85,41.07 ; R38.1 74.9,25.2 ; R38.1 75.55,26.05 ; R38.1 75.55,23.9 C41.1 74.5,23.8 ; R11.1 61.1,33.3 ; 39.6,25.3 39.6,26.55 ; v1(76.6,5.8) 77.15,6.35 C14.1 77.17,7.08 C13.1 77.59,8.77 v1(77.95,9.25) ; D3.2 86.6,15.35 ; D3.2 87.55,16 ; D3.2 R14.1 85.2,15.3 ; C5.1 82.25,8.3 ; C5.1 81.38,9.4 ; v1(39.05,32.15) 39.17,32.02 C29.1 ; 39.6,26.55 39.6,28.16 v1(39.75,28.3) ; 39.6,26.55 40.35,26.55 40.65,26.85 ; C26.1 51.62,32.33 v1(52.2,32.9) ; v1(79.65,25.4) 79.77,25.87 C42.1 ; C25.1 47.58,30.02 v1(47.75,29.85) ; C30.1 34.85,30.18 ; 11.5,35.85 11.15,35.5 C61.1 10.5,36.56 v1(10.53,36.58) ; 21.25,36.5 R60.1 20.4,37.3 ; Q5.2 75.75,20.75 R37.1 ; 15.45,35.95 C60.1 16.45,36.9 ; 82.5,18.4 C11.1 81.7,17.4 ; CN1.1 93.3,19.55 ; CN1.1 92.05,18.3 ; CN1.1 93.3,16.75 ; CN1.1 95,18.3 ; R37.1 76.55,19.6 ; R37.1 75.75,18.6 ; 86.6,22.2 D2.2 87.45,22.9 ; v1(31.25,37.35) 30.8,36.9 R20.1 30.8,34.05 Q3.2 ; R59.1 16.6,38.2 ; 87.5,19.65 D4.2 86.6,18.65 ; C10.1 v1(83.9,22.1) ; 70.5,24.7 R39.1 69.65,25.5 ; Q6.2 v1(16.4,42.55) ; R13.1 85.2,22.25
  TOP w0.6: 78.13,20.3 81.6,23.77
  CONDUCTIVE2 w0.5: 94.55,18.3 CN1.1 93.3,17.05
  BOTTOM w0.3: C15.1 82.22,9.53 82.65,9.95 ; v1(72.85,11.9) 73.75,12.8 74.94,12.8 77.4,10.34 77.4,9.8 v1(77.95,9.25) ; IC2.2 80.95,12.8 80.62,13.13 80.41,13.13 80.41,13.22 v1(79.99,13.38) ; Q1.2 83.6,24.9 83.13,25.37 v1(83.13,25.68)
  BOTTOM w0.5: D5.2 86.5,14.65 C20.1 ; 80,18.9 C4.1 81.1,21 v1(81.25,21) 81.25,21.25 81.65,21.65 C9.1 82.75,22.1 v1(83.9,22.1) ; 76.05,24.1 C6.1 77.12,25.12 76.9,25.35 ; 88.1,19.45 D1.2 87,18.55 ; v1(83.05,18.6) 83.3,18.05 83.3,17.48 ; C22.1 84.9,15.35 ; C21.1 74.88,18.2 v1(74.63,18.44) ; v1(88,22.35) D6.2 85.38,22.35 C7.1 84.4,22.52 ; v1(82.5,7.45) 82.22,7.98 C15.1 ; C17.1 74.65,16.8 ; C200.1 85,12.8
  BOTTOM w1: D7.1 93.5,15.75 ; D7.1 93.5,13.1 ; D7.1 95.35,14.5 v1(95.4,14.55)
  BOTTOM w1.2: 94.9,18.3 CN1.1 93.3,16.64
  vias: v1(1.4,48.73) v1(1.4,42.82) v1(1.4,36.91) v1(1.4,31) v1(1.65,53.9) v1(3.85,27.12) v1(6.1,31.2) v1(6.4,54.65) v1(6.4,42.82) v1(6.4,36.91) v1(6.85,29.65) v1(7.85,29.65) v1(8.45,60.6) v1(11.4,54.65) v1(11.4,42.82) v1(12.6,38.4) v1(13.58,60.6) v1(14.3,34) v1(14.3,32) v1(15.5,34) v1(15.5,32) v1(16.4,54.65) v1(16.6,37.65) v1(16.6,36.45) v1(17.2,60.5) v1(17.8,37.65) v1(17.9,42.5) v1(21.25,42.85) v1(22.1,37.35) v1(22.12,35.55) v1(23.05,33.35) v1(23.55,29) v1(25.75,27.05) v1(26.35,42.85) v1(29,36.4) v1(29.25,38.5) v1(30,36.4) v1(32.9,31.7) v1(33.25,38.5) v1(34.5,30.85) v1(34.5,29.85) v1(37.7,36.29) v1(39.1,34.35) v1(40.1,34.35) v1(41.81,28.75) v1(44.8,35.74) v1(45.9,29.85) v1(52.35,35.35) v1(55.5,29.19) v1(59.4,21.45) v1(59.8,35.24) v1(61.1,33.7) v1(61.5,20.94) v1(62.35,30.05) v1(63.75,19.59) v1(63.9,23.5) v1(65.4,35.19) v1(66.5,31.45) v1(67.15,35.2) v1(67.7,19.24) v1(68.45,24.25) v1(72.85,21.25) v1(73.45,25.85) v1(74.28,1.4) v1(74.65,25.85) v1(74.81,9.19) v1(75.4,30) v1(75.4,28) v1(75.8,14.1) v1(76.6,30) v1(76.6,28) v1(76.7,20.2) v1(78.2,13.4) v1(80.35,1.4) v1(82.1,3.15) v1(83.8,14.45) v1(83.8,13.25) v1(83.95,31.95) v1(84.95,31.95) v1(85,14.45) v1(85,13.25) v1(85.8,35.39) v1(86.02,18.69) v1(86.2,25.75) v1(86.42,1.4) v1(86.75,28.05) v1(87.2,32.05) v1(87.8,6.09) v1(88.2,32.05) v1(89.4,3.25) v1(91.15,5.04) v1(91.25,1.4) v1(95.4,15.75) v1(96.35,31.65) v1(96.35,30.65) v1(96.6,15.75) v1(96.6,14.55) v1(96.95,27.2) v1(96.95,12.4) v1(97.15,21.5) v1(98.6,35.55) v1(98.6,31) v1(98.6,25.09) v1(98.6,19.18) v1(98.6,13.27) v1(98.6,7.7)
VDD: length 37.2
  TOP w0.5: v1(87.25,9.45) 85.65,7.85 TP6.1 ; v1(84.3,26.85) 84.08,26.63 82.06,26.63 80.9,25.47 80.9,24.75 R29.2 ; R50.2 v1(12.25,41)
  BOTTOM w0.5: IC5.1 34.05,34.5 34.45,34.9 34.45,35.95 34,36.4 IC5.3 ; IC1.3 44.31,34.8 44.65,34.46 44.65,33.24 44.31,32.9 IC1.1
  BOTTOM w1: D7.2 90.7,13.5 ; D7.2 89.7,14.5 ; D7.2 90.7,15.6
  BOTTOM w1.5: 12.3,28.65 T2.4 T2.5 9.6,28.55 ; CN1.2 90.76,16.2 ; 81.3,33.4 T1.5 T1.4 78.6,33.45
  vias: v1(7.5,34.7) v1(7.5,33.7) v1(8.5,34.7) v1(8.5,33.7) v1(28.65,34.9) v1(28.65,33.7) v1(29.85,34.9) v1(29.85,33.7) v1(40.2,32.55) v1(40.2,31.35) v1(40.2,30.15) v1(84.3,27.85) v1(85.3,27.85) v1(85.3,26.85) v1(87.25,10.65) v1(88.45,10.65) v1(88.45,9.45)
VEE_A: length 15.3
  TOP w0.5: Q26.2 44.5,53.4 R185.1 v1(42.45,53.4) ; v1(59.35,51.5) 58.8,51.75 57.8,51.75 ; C23.1 v1(55.42,54.65)
  CONDUCTIVE3 w0.3: CN2.5 54.05,58.7 ; CN2.5 52.89,57.5 ; CN2.5 52.89,59.95 ; CN2.5 CN2.6 ; CN2.6 50.35,57.5 ; CN2.6 49.2,58.7 ; CN2.6 50.35,59.95
  vias: v1(77.2,60.05) v1(77.2,58.85)
VEE_B: length 15.5
  TOP w0.5: v1(27.6,10.45) 28.37,10.25 29.05,10.25 ; v1(34,7.42) 33.6,7.03 C27.1 ; Q32.2 42.35,8.6 v1(42.9,9.15) 43.43,8.87 R186.1
  CONDUCTIVE3 w0.3: CN3.6 45.85,4.5 ; CN3.6 CN3.5 ; CN3.6 46.95,3.25 ; CN3.6 45.85,1.85 ; CN3.5 42.2,3.25 ; CN3.5 43.31,1.9 ; CN3.5 43.31,4.5
  vias: v1(9.35,2.85) v1(10.35,2.85) v1(11.35,2.85) v1(13,2.85) v1(14,2.85) v1(15,2.85) v1(16,2.85) v1(17,2.85) v1(18,2.85)
A_ENA: length 12.6
  BOTTOM w0.3: R10.1 83.9,21.05 R12.1 85.3,21.15 D1.1 88.65,21.15 89.25,21.75 89.25,23.5 90.4,24.65 92.03,24.65 CN1.7
A_FLT: length 11
  BOTTOM w0.3: R2.1 81.42,23.02 83.83,23.02 84.67,23.88 C7.2 85.38,24.05 D6.1 88.67,25.92 CN1.8
A_INA: length 10
  TOP w0.3: R9.1 84,24.5 R13.2 85.3,24.6 D2.1 86.8,24.6 86.9,24.7 92.05,24.7 92.59,24.16 CN1.5
ANODE_A: length 5.1
  TOP w0.3: R1.1 54,31.75 R5.2 55.15,31.85 C3.2 55.27,33.37 55.27,35.45
ANODE_B: length 6
  TOP w0.3: IC10.2 31.59,28.98 C16.2 31.75,29.35 R18.2 R15.1
B_ENA: length 7.8
  TOP w0.3: R7.1 84.15,21.25 R4.1 85.4,21.35 D4.1 88.73,21.35 CN1.6
B_FLT: length 15.9
  BOTTOM w0.3: CN1.3 92.03,19.57 89.57,19.57 87.65,17.65 D5.1 85.08,17.65 C22.2 84.22,17.48 84,17.25 84,16.57 83.75,16.32 Q4.3 81.28,16.32 R16.1 R107.1
B_INA: length 8.3
  TOP w0.3: R6.1 83.95,17.5 R14.2 85.4,17.7 D3.1 87.62,17.7 CN1.4
CATHODE_A: length 8.2
  TOP w0.3: 56.8,31.8 R5.1 ; 56.8,31.8 Q2.3 TP3.1 ; 56.8,31.8 56.85,31.85 C3.1 56.53,33.56 56.53,35.45
CATHODE_B: length 10.3
  TOP w0.3: Q3.3 28.8,32.4 TP7.1 29.45,30.75 R18.1 30.25,29.35 C16.1 30.32,29.09 30.32,26.4
FAULT_2_A: length 4.5
  TOP w0.3: CN2.9 40.75,56.72 R149.1
FAULT_2_B: length 8.1
  TOP w0.3: R174.1 49.87,6.85 CN3.9
FAULT_A: length 41.4
  TOP w0.2: 47.95,32.67 47.38,32.67 47.1,32.4
  TOP w0.3: 47.1,32.4 46.8,32.1 46.8,29.01 49.06,26.75 67.2,26.75 v2(68.45,25.5)
  BOTTOM w0.3: v2(68.45,25.5) 71.2,22.75 R3.1 78.5,24.07 C6.2 R8.2
FAULT_B: length 45.9
  TOP w0.2: 39.7,29.15 39.42,29.15 IC12.4
  TOP w0.3: 39.7,29.15 40.15,29.15 46.75,22.55 70.1,22.55 v1(71.35,21.3)
  BOTTOM w0.3: R19.2 78.35,17.4 R17.1 77.55,18.2 C21.2 76.97,18.62 76.2,19.4 73.25,19.4 v1(71.35,21.3)
FYB_DISABLE_A: length 12.8
  TOP w0.3: Q5.1 74.25,20.75 R37.2 73.7,19.05 73.7,10.9 74.5,10.1 IC3.4
FYB_DISABLE_B: length 80.3
  TOP w0.3: v2(74.7,11) 76.8,11 77.05,10.75 IC3.6 ; v2(62.75,24.95) 62.35,25.35 48.48,25.35 44.94,28.89 44.94,29.81 42.85,31.9 42.85,36.15 39.43,39.57 R58.2 16.43,39.57 Q6.1
  BOTTOM w0.3: v2(62.75,24.95) 62.75,18.09 69.84,11 v2(74.7,11)
IN2_N_A: length 16
  TOP w0.3: CN2.8 47.87,56.1 55.44,56.1 56.53,55 56.53,51.75
IN2_N_B: length 25.3
  TOP w0.3: 30.32,10.25 30.32,7.18 32.5,5 49.18,5 CN3.8
SIG00005: length 1.6
  BOTTOM w0.3: Q1.1 81.28,24.18 R8.1
SIG00006: length 33
  TOP w0.3: v2(81,18.5) 81,13.94 81.85,13.09 81.85,10.65 82.13,10.37 IC4.2 83.38,10.37 83.75,10 v2(83.75,9.05) ; v2(74.45,12.05) 75.05,12 IC3.3
  BOTTOM w0.3: R10.2 82.6,19.65 C9.2 81.75,19.95 81,19.2 v2(81,18.5) ; v2(83.75,9.05) 84.5,8.3 84.5,7.4 83.1,6 78.55,6 76.55,8 76.55,10.34 74.84,12.05 v2(74.45,12.05)
SIG00008: length 5.8
  TOP w0.3: R6.2 82.55,16.05 C11.2 v2(82.5,14.35)
  BOTTOM w0.3: v2(82.5,14.35) 81.6,13.45 IC2.3
SIG00010: length 34.5
  TOP w0.3: v2(61.1,30) R11.2 60.05,31.05 Q2.1 ; IC4.7 78.97,10.37 v2(78.7,10.1)
  BOTTOM w0.3: v2(61.1,30) 64.85,26.25 64.85,17.97 69.32,13.5 75.09,13.5 78.18,10.41 v2(78.7,10.1)
SIG00011: length 83.9
  TOP w0.3: v2(83.75,11.25) 83.36,10.87 IC4.3 ; v2(60.35,23.95) 47.9,23.95 41.65,30.2 41.65,34 38,37.65 32.65,37.65 32.3,37.3 R20.2 32.3,34.05 Q3.1
  BOTTOM w0.3: v2(60.35,23.95) 60.35,18.35 70.5,8.2 72.45,8.2 76.2,4.45 83.35,4.45 85.7,6.8 85.7,9.3 v2(83.75,11.25)
SIG00012: length 1.5
  BOTTOM w0.3: 82.5,17.48 81.12,17.48 R19.1
SIG00015: length 1.5
  BOTTOM w1: CN1.9 93.3,30
SIG00017: length 1.5
  BOTTOM w1: CN1.10 90.76,30
SIG00026: length 2
  TOP w0.2: 48.52,35.45 48.65,35.31 IC8.1
SIG00036: length 2.3
  TOP w0.2: 38.34,26.55 38.34,26.85 38.25,26.93 IC12.1
SIG00040: length 4.9
  BOTTOM w0.6: D13.2 73.95,30 74.95,31 77.05,31 77.55,30.5 D10.1
SIG00041: length 4.2
  BOTTOM w0.6: 78,31.8 77.9,31.9 74.15,31.9 C36.2
SIG00042: length 3.6
  TOP w1.5: 70.15,51.98 T1.15 71.64,54.1
SIG00044: length 14
  TOP w1: 60.51,57.05 CN2.2 CN2.1 ; CN2.1 64.75,58.7 ; CN2.1 63.05,57.05
  BOTTOM w1: 60.51,57.65 CN2.2 CN2.1 ; CN2.1 63.05,57.1 ; CN2.1 64.3,58.7
  vias: v1(61.55,56.7) v1(61.55,55.5) v1(62.75,56.7) v1(62.75,55.5)
SIG00050: length 4.3
  TOP w1.5: 82.05,51.98 T1.12 79.64,53.85
SIG00052: length 8.1
  TOP w0.5: IC16.1 78.6,25.75 78.05,25.2 R38.2 77.05,23.9 C41.2 77.05,23.7 R29.1 Q5.3
SIG00053: length 2
  TOP w0.5: C42.2 79.8,27.9 79.33,28.36 IC16.2
SIG00054: length 2.7
  TOP w0.3: IC16.8 73.14,27.09 72.55,26.5 72.55,25.69 72.36,25.5 R32.2
SIG00055: length 2.5
  TOP w0.3: IC16.6 72.64,29.64 71.65,28.65 R36.2
SIG00056: length 1.2
  TOP w0.3: R36.1 R40.2
SIG00057: length 13.4
  TOP w0.5: R40.1 69,30.75
  TOP w1.5: T1.1 70.5,33 ; T1.2 73.2,32.5
  BOTTOM w1.5: 73.2,33.8 T1.2 T1.1 ; T1.1 70.5,33.45 ; T1.1 68.8,35.2
  vias: v1(68.45,31.85) v1(68.45,30.85) v1(69.45,31.85) v1(69.45,30.85)
SIG00057_502750: length 12.8
  TOP w0.5: R61.1 21.7,31.2
  TOP w1.5: T2.1 20.4,28.75 ; T2.2 17.7,28.75
  BOTTOM w1.5: T2.1 21.9,26.8 ; T2.1 T2.2 17.7,28.25 ; T2.1 20.4,29.05
  vias: v1(21.25,31.25) v1(21.25,30.25) v1(22.25,31.25) v1(22.25,30.25)
SIG00058: length 3.8
  TOP w0.3: IC16.7 72.67,28.36 72.35,28.05 72.35,27.55 R32.1
  TOP w0.5: R32.1 R39.2
SIG00061: length 5
  BOTTOM w0.6: D18.1 13.35,31.5 13.95,30.9 15.85,30.9 16.95,32 D21.2
SIG00062: length 4.3
  BOTTOM w0.6: C55.2 16.65,30 13.55,30 13.35,30.2 12.9,30.2
SIG00063: length 3.3
  BOTTOM w1.5: 19.26,8.3 T2.15 20.85,10.02
SIG00065: length 7.6
  BOTTOM w1: 35.69,4.9 CN3.2 CN3.1 ; CN3.1 33.15,4.95 ; CN3.1 31.45,3.25
SIG00071: length 6.6
  TOP w1.5: 11.26,8.9 T2.12 9.45,10.02
  BOTTOM w1.5: 11.26,8.8 T2.12 8.85,10.02
SIG00073: length 7.2
  TOP w0.3: IC20.1 12.3,36.15 13.05,36.9 C60.2 13.75,38.1 R59.2 13.75,38.3 R50.1 14.25,40.1 Q6.3
SIG00074: length 2
  TOP w0.3: IC20.2 11.56,33.63 11.1,34.1 C61.2
SIG00075: length 2.7
  TOP w0.3: IC20.8 18.15,35.55 18.15,36.25 18.4,36.5 R53.2
SIG00076: length 2.4
  TOP w0.3: IC20.6 18.36,32.37 19.05,33.05 R57.2
SIG00077: length 1.2
  TOP w0.3: R57.1 20.65,33.75 R61.2
SIG00079: length 3.5
  TOP w0.3: IC20.7 17.84,33.63 18.5,34.3 18.5,34.4 R53.1
  TOP w0.5: R53.1 R60.2
SIG00190: length 2.9
  TOP w0.3: Q26.1 43.8,54.95 R185.2 42.35,54.9 R149.2
SIG00227: length 3.1
  TOP w0.3: R174.2 43.95,6.85 R186.2 Q32.1
SIG00236: length 18.3
  TOP w0.3: IC3.1 77.05,11.6 77.78,10.87 IC4.6 80.6,10.87 80.75,11.02 80.75,12.05 80.4,12.4 79.77,12.4 79.14,13.03 79.14,18.55 80.59,20 82.1,20 C12.2 82.45,19.85 R7.2
SIG00237: length 17.4
  TOP w0.3: R9.2 82.5,24.4 C10.2 82.04,23.15 77.1,18.21 v2(77.1,13.4)
  BOTTOM w0.3: IC2.1 79.68,12.02 79.15,12.55 77.85,12.55 77.47,12.93 v2(77.1,13.4)
SIG00238: length 5.4
  TOP w0.3: v2(78.7,11.8) 79.13,11.37 IC4.5
  BOTTOM w0.3: IC2.4 81.6,10.72 81.22,11.1 79.75,11.1 79.05,11.8 v2(78.7,11.8)
SIG00239: length 13.2
  TOP w0.3: v2(83.75,7.85) 82.65,8.95 IC4.1
  BOTTOM w0.3: v2(83.75,7.85) 83.75,7.5 82.85,6.6 78.8,6.6 78.1,7.3 78.1,8.05 78.55,8.5 79.2,8.5 80.3,9.6 IC2.6
VE_A: length 48.4
  TOP w0.5: C46.2 73.15,56.9 ; C46.2 74.05,55.7 ; C46.2 C45.2 ; C45.2 74.05,60.1 ; C45.2 73.15,58.9
  TOP w1: CN2.3 59,58.7 ; CN2.3 57.97,60.2 ; CN2.3 CN2.4 ; CN2.3 57.97,57.2 ; CN2.4 55.43,59.75 ; CN2.4 55.43,57.35
  TOP w1.5: T1.13 77.39,53.8 ; T1.14 73.89,53.75
  CONDUCTIVE2 w0.3: CN2.4 55.43,60.05 ; CN2.4 CN2.3 ; CN2.4 55.43,57.35 ; CN2.4 54.25,58.7 ; CN2.3 59.05,58.7 ; CN2.3 57.97,57.5 ; CN2.3 57.97,60.15
  CONDUCTIVE2 w1: T1.13 77.39,54.3 ; T1.14 73.89,54.2
  BOTTOM w1: CN2.3 57.97,60.2 ; CN2.3 CN2.4 ; CN2.3 57.97,57.65 ; CN2.4 55.43,60.25 ; CN2.4 55.43,57.1 ; 77.39,53.55 T1.13 T1.14 73.89,53.6
  vias: v1(57.55,56.8) v1(57.55,55.6) v1(61.7,51.5) v1(62.9,51.5) v1(64.1,51.5) v1(65.3,51.5) v1(66.5,51.5) v1(72.8,59.6) v1(72.8,58.4) v1(72.8,57.2) v1(74.28,60.6)
VE_B: length 23.6
  TOP w1.5: T2.14 17.01,8.41 ; T2.13 13.51,8.5
  CONDUCTIVE2 w0.5: CN3.3 CN3.4 ; CN3.3 38.23,2 ; CN3.3 37.15,3.25 ; CN3.3 38.23,4.5 ; CN3.4 40.77,1.95 ; CN3.4 41.85,3.25 ; CN3.4 40.77,4.45
  CONDUCTIVE2 w1: T2.13 13.51,7.65 ; T2.14 17.01,8.3
  BOTTOM w1: 17.01,8.2 T2.14 T2.13 13.51,8.65
  vias: v1(12.2,7.65) v1(13.2,7.65) v1(16.05,6.8) v1(17.05,6.8) v1(18.05,6.8) v1(23.15,10.3) v1(24.15,10.3) v1(25.35,9.15) v1(26.35,9.15) v1(27.35,9.15) v1(28.35,8.75) v1(29.35,8.85) v1(31.5,8.75)
VL_A: length 14.2
  TOP w0.5: v1(54.08,54.65) C23.2 53.99,53.42 53.99,51.75 ; R141.2 v1(52.55,53.6)
  BOTTOM w1: CN2.7 47.81,56.54 50.75,53.6 v1(52.55,53.6) 53.02,53.6 v1(54.08,54.65)
VL_B: length 21.9
  TOP w0.5: v1(34,8.78) 33.6,8.38 C27.2 32.9,8.78 32.85,8.82 32.85,10.25 ; R166.2 35.05,8.23 v1(35.3,8.78)
  BOTTOM w1: CN3.7 44.49,7.15 40.08,7.15 38.45,8.78 v1(35.3,8.78) v1(34,8.78)
N02405: length 5.3
  TOP w0.3: 49.78,51.75 49.78,53.34 C125.2 50.85,53.5 51.05,53.7 R141.1 R145.2
N76786: length 5.2
  TOP w0.3: 48.52,51.75 48.52,53.23 C125.1 48.25,54.7 R145.1 46.8,54.8 Q26.3
N938622: length 4.8
  TOP w0.3: 37.06,10.25 37.06,8.38 C145.2 37.65,7.8 R170.2 R166.1
N938626: length 5.8
  TOP w0.3: 38.34,10.25 38.34,9.41 38.85,8.9 C145.1 38.85,7.1 R170.1 40.35,6.8 Q32.3

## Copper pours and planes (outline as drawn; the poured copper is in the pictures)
5V_A on TOP: 49.04,28.58 49,28.59 48.97,28.61 48.67,28.9 48.62,28.99 48.6,29.08 48.6,30.75 48.63,30.82 48.7,30.85 49.2,30.85 49.45,30.95 49.55,31.2 49.55,31.8 49.51,31.96 49.39,32.09 49.38,32.1 49.36,32.14 49.35,32.17 49.35,32.4 49.32,32.56 49.21,32.73 49.2,32.77 49.2,33.75 49.27,33.93 49.45,34 50.25,34 50.32,33.97 50.35,33.9 50.35,32.05 50.45,31.8 50.7,31.7 51.65,31.7 51.83,31.63 52,31.2 52.25,31.1 52.65,31.1 52.69,31.1 52.73,31.11 52.81,31.09 52.85,31.01 52.85,30.46 52.81,30.38 51.6,30.13 51.1,29.1 51.1,28.83 51.03,28.65 50.85,28.58
5V_A on TOP: 73.34,2.3 73.3,2.31 73.27,2.33 67.32,8.28 67.28,8.33 67.25,8.45 67.25,17.35 67.28,17.48 67.38,17.57 67.5,17.6 71.6,17.6 71.72,17.57 71.82,17.48 71.85,17.35 71.85,11.15 71.88,11.03 71.92,10.98 75.07,7.83 75.09,7.8 75.1,7.76 75.1,6.75 75.2,6.51 75.45,6.4 75.98,6.4 76.07,6.35 76.06,6.24 76.2,5.23 77.2,5.44 77.46,5.87 77.54,5.96 77.66,6.14 77.7,6.35 77.7,6.47 77.71,6.51 77.72,6.53 77.78,6.64 77.8,6.75 77.8,7.35 77.79,7.45 77.73,7.57 77.72,7.6 77.72,7.8 77.73,7.83 77.78,7.95 77.8,8.05 77.83,8.12 77.9,8.14 78.05,8.14 78.1,8.15 79.1,8.15 79.22,8.12 79.32,8.03 79.35,7.9 79.35,6.6 79.45,6.36 79.7,6.25 80.3,6.25 80.37,6.22 80.4,6.15 80.4,2.89 80.39,2.85 80.37,2.82 79.88,2.33 79.85,2.31 79.81,2.3
5V_A on BOTTOM: 49.05,28.75 48.99,28.76 48.88,28.82 48.48,29.22 48.46,29.25 48.45,29.29 48.45,29.76 48.45,29.81 48.25,30.34 47.73,30.55 47.72,30.55 45.5,30.55 45.46,30.55 45.42,30.56 45.37,30.6 45.35,30.66 45.35,33.05 45.38,33.17 45.48,33.27 45.6,33.3 50.11,33.3 50.15,33.29 50.18,33.27 50.73,32.72 50.77,32.67 50.8,32.55 50.8,28.85 50.77,28.78 50.7,28.75
5V_A on BOTTOM: 70.1,15.2 69.97,15.23 69.88,15.32 69.85,15.45 69.85,16.95 69.88,17.07 69.97,17.17 70.1,17.2 71.58,17.2 71.62,17.19 71.65,17.17 71.82,17 71.84,16.97 71.85,16.93 71.85,15.45 71.82,15.32 71.72,15.23 71.6,15.2
5V_A on BOTTOM: 94.9,33.2 94.78,33.23 94.68,33.33 94.65,33.45 94.65,34.4 94.68,34.52 94.78,34.62 94.9,34.65 97.2,34.65 97.33,34.62 97.42,34.52 97.45,34.4 97.45,33.45 97.42,33.33 97.33,33.23 97.2,33.2
5V_A on CONDUCTIVE3: outline of 117 points within 48.7,14.28 84.95,31.3 ; 9 cut-outs
5V_B on TOP: 35.5,27.8 35.43,27.83 35.4,27.9 35.4,28.05 35.41,28.16 35.49,28.2 36.05,28.2 36.3,28.3 36.4,28.55 36.4,30.45 36.36,30.61 36.15,30.78 36.05,30.8 36.03,30.8 35.99,30.81 35.96,30.83 35.95,30.84 35.91,30.91 35.9,30.99 35.9,32.85 35.9,33.75 35.93,33.88 36.02,33.97 36.15,34 38.2,34 38.26,33.98 38.3,33.88 38.3,31.9 38.23,31.72 38.05,31.65 37.55,31.65 37.3,31.55 37.2,31.3 37.2,30.7 37.3,30.45 37.55,30.35 38.15,30.35 38.31,30.29 38.4,30.14 38.4,30.12 38.37,30.05 38.3,30.02 38.2,30.02 37.95,29.92 37.85,29.68 37.85,29 37.81,28.87 37.8,28.77 37.8,28.29 37.79,28.25 37.77,28.22 37.42,27.87 37.34,27.82 37.25,27.8
5V_B on BOTTOM: 86.8,33.05 86.67,33.08 86.58,33.17 86.55,33.3 86.55,34.35 86.58,34.48 86.67,34.57 86.8,34.6 89.25,34.6 89.38,34.57 89.47,34.48 89.5,34.35 89.5,33.3 89.47,33.17 89.38,33.08 89.25,33.05
5V_B on CONDUCTIVE3: outline of 102 points within 35.1,22.95 77.51,40.1 ; 7 cut-outs
GND on TOP: outline of 200 points within 1,1 99,61 ; 14 cut-outs
GND on TOP: 77.84,12.69 77.66,12.76 77.59,12.94 77.59,13.02 77.59,13.04 77.6,13.07 77.69,13.3 77.55,14.04 77.55,14.07 77.55,17.98 77.56,18.02 77.58,18.05 82.02,22.49 82.06,22.51 82.11,22.51 82.16,22.5 82.2,22.5 84.2,22.5 84.26,22.5 84.74,22.5 84.76,22.5 84.87,22.46 84.95,22.45 85.89,22.45 85.95,22.44 86.11,22.33 86.25,22.3 86.95,22.3 87.2,22.4 87.3,22.65 87.3,24 87.37,24.18 87.55,24.25 89.15,24.25 89.33,24.18 89.4,24 89.4,22.7 89.39,22.66 89.37,22.63 88.57,21.83 88.54,21.81 88.5,21.8 87.29,21.8 87.25,21.81 87.21,21.83 87.09,21.92 86.95,21.95 86.25,21.95 86.11,21.92 85.99,21.83 85.95,21.81 85.91,21.8 85.05,21.8 84.93,21.78 84.8,21.71 84.77,21.7 84.15,21.7 84.05,21.69 83.92,21.65 82.25,21.65 82,21.55 81.9,21.3 81.9,20.8 81.92,20.7 81.96,20.61 81.97,20.58 81.96,20.49 81.88,20.45 80.59,20.45 80.42,20.42 80.27,20.32 78.83,18.87 78.73,18.72 78.69,18.55 78.69,13.03 78.7,12.93 78.74,12.82 78.73,12.73 78.65,12.69
GND on BOTTOM: outline of 231 points within 1,1 99,61 ; 8 cut-outs
GND on BOTTOM: 87.69,21.6 87.65,21.61 87.55,21.69 87.47,21.73 87.41,21.8 87.43,21.88 87.48,21.99 87.5,22.1 87.5,24.07 87.51,24.11 87.53,24.14 88.83,25.44 88.86,25.46 88.9,25.47 89.25,25.47 89.29,25.46 90.06,25.13 90.12,25.06 90.09,24.97 88.93,23.81 88.83,23.67 88.8,23.5 88.8,21.98 88.79,21.94 88.77,21.91 88.49,21.63 88.46,21.61 88.42,21.6
GND on BOTTOM: 80.75,20.1 80.68,20.13 80.55,20.45 80.3,20.55 80.05,20.55 79.98,20.58 79.95,20.65 79.95,21.53 79.95,21.56 80.03,21.71 80.05,21.85 80.05,21.99 80.07,22.05 80.12,22.09 80.16,22.1 80.2,22.1 81.3,22.1 81.38,22.11 81.46,22.14 81.55,22.13 81.6,22.05 81.6,20.44 81.59,20.39 81.55,20.35 81.49,20.31 81.43,20.27 81.29,20.13 81.26,20.11 81.22,20.1
GND on CONDUCTIVE2: outline of 90 points within 1,1 99,61 ; 31 cut-outs
GND on CONDUCTIVE3: 86.55,25.94 86.55,25.92 86.55,25.58 86.55,25.56 86.53,25.53 85.8,25.75 86.53,25.97
GND on CONDUCTIVE3: outline of 124 points within 65,1 99,40.09 ; 1 cut-out
GND on CONDUCTIVE3: outline of 113 points within 1,21.9 34.81,61 ; 1 cut-out
GND on CONDUCTIVE3: 12.24,38.36 12.32,38.4 12.88,38.4 12.96,38.36 12.98,38.27 12.6,38 12.22,38.27
GND on CONDUCTIVE3: 76.2,5.8 77,5.8
GND on CONDUCTIVE3: 87.4,6.09 88.2,6.09
GND on CONDUCTIVE3: 86.55,28.04 86.45,27.94 86.35,28.04 86.35,28.06 86.45,28.16 86.55,28.06
VDD on TOP: 11.19,31.95 11.15,31.96 11.12,31.98 10.97,32.13 10.86,32.19 10.8,32.2 7.3,32.2 7.17,32.23 7.08,32.33 7.05,32.45 7.05,35.4 7.08,35.52 7.17,35.62 7.3,35.65 9.6,35.65 9.72,35.62 9.82,35.52 9.85,35.4 9.85,33.8 9.95,33.55 10.2,33.45 10.8,33.45 10.83,33.45 11.02,33.48 11.06,33.48 11.11,33.46 11.25,33.32 11.32,33.26 11.4,33.22 11.43,33.19 11.46,33.16 11.59,33.01 11.78,32.95 12.7,32.95 12.82,32.92 12.92,32.83 12.95,32.7 12.95,32.05 12.92,31.98 12.85,31.95
VDD on TOP: 87.1,9.05 86.97,9.08 86.88,9.18 86.85,9.3 86.85,10.8 86.88,10.93 86.97,11.02 87.1,11.05 88.6,11.05 88.72,11.02 88.82,10.93 88.85,10.8 88.85,9.3 88.82,9.18 88.72,9.08 88.6,9.05
VDD on TOP: 81.3,25.7 81.17,25.73 81.08,25.82 81.05,25.95 81.05,28.2 80.95,28.45 80.7,28.55 80.1,28.55 80.07,28.55 79.95,28.54 79.91,28.57 79.72,28.75 79.59,28.85 79.4,28.92 79.38,28.94 79.26,29.02 79.12,29.05 78.2,29.05 78.08,29.08 77.98,29.17 77.95,29.3 77.95,29.95 77.98,30.02 78.05,30.05 79.71,30.05 79.75,30.04 79.78,30.02 79.93,29.87 80.04,29.81 80.1,29.8 85.45,29.8 85.58,29.77 85.67,29.68 85.7,29.55 85.7,26.45 85.67,26.38 85.6,26.35 83.34,26.35 83.31,26.35 83.13,26.38 82.95,26.35 82.92,26.35 82.38,26.35 82.15,26.3 81.96,26.17 81.51,25.73 81.48,25.71 81.44,25.7
VDD on BOTTOM: 28.73,32.28 28.66,32.29 28.55,32.35 28.18,32.72 28.16,32.75 28.15,32.79 28.15,34.96 28.16,35 28.18,35.03 28.38,35.23 28.43,35.27 28.55,35.3 30.95,35.3 31.01,35.29 31.12,35.23 31.23,35.12 31.34,35.06 31.4,35.05 32.11,35.05 32.15,35.04 32.18,35.02 32.35,34.85 32.49,34.85 32.55,34.85 33.35,34.85 33.42,34.82 33.45,34.75 33.45,33.47 33.44,33.43 33.42,33.4 32.37,32.35 32.32,32.31 32.2,32.28
VDD on BOTTOM: 8.99,28.1 8.95,28.11 8.92,28.13 8.58,28.47 8.56,28.5 8.55,28.54 8.55,29.6 8.55,29.6 8.51,29.89 8.35,30.14 6.91,31.58 6.87,31.63 6.84,31.75 6.84,34.76 6.85,34.8 6.87,34.83 7.22,35.18 7.27,35.22 7.39,35.25 9.01,35.25 9.05,35.24 9.08,35.22 11.43,32.87 11.47,32.82 11.5,32.7 11.5,30.97 11.51,30.91 11.59,30.79 11.6,30.73 11.6,29.95 12.1,29.45 12.81,29.45 12.85,29.44 12.88,29.42 13.06,29.24 13.08,29.21 13.09,29.17 13.09,28.44 13.08,28.4 13.06,28.37 12.81,28.13 12.78,28.11 12.74,28.1
VDD on BOTTOM: 39.8,32.8 39.81,32.86 39.87,32.97 40.53,33.63 40.55,33.65 40.59,33.66 40.72,33.68 40.89,33.75 41.9,33.75 41.96,33.74 42.07,33.68 42.43,33.32 42.54,33.26 42.6,33.25 43.85,33.25 43.92,33.22 43.95,33.15 43.95,32.11 43.93,32.04 43.65,31.89 43.56,31.66 43.56,31.59 43.56,31.56 43.53,31.52 41.82,29.81 41.77,29.77 41.65,29.74 40.05,29.74 39.92,29.77 39.83,29.86 39.8,29.99
VDD on BOTTOM: 81.85,26.4 81.79,26.41 81.68,26.47 79.47,28.68 79.43,28.73 79.4,28.85 79.4,31.03 79.39,31.09 79.31,31.21 79.3,31.27 79.3,32.05 79.23,32.23 79.05,32.3 78.67,32.3 78.63,32.31 78.6,32.33 77.83,33.1 77.81,33.13 77.8,33.17 77.8,33.8 77.83,33.87 77.9,33.9 82.21,33.9 82.25,33.89 82.28,33.87 82.62,33.53 82.64,33.5 82.65,33.46 82.65,31.95 85.73,28.87 85.78,28.79 85.8,28.7 85.8,26.5 85.77,26.43 85.7,26.4
VDD on BOTTOM: 87,9 86.88,9.03 86.78,9.12 86.75,9.25 86.75,11.4 86.75,11.43 86.79,11.49 87.33,12.03 87.39,12.14 87.4,12.2 87.4,15.8 87.41,15.86 87.47,15.97 89.17,17.67 89.2,17.69 89.24,17.7 91.4,17.7 91.47,17.67 91.5,17.6 91.5,15.47 91.46,15.39 91.37,15.38 91.31,15.39 91.25,15.4 90.15,15.4 89.9,15.3 89.8,15.05 89.8,13.95 89.9,13.7 90.15,13.6 91.15,13.6 91.22,13.57 91.25,13.5 91.25,12.42 91.23,12.36 89.74,11.18 89.2,9.43 89.2,9.25 89.17,9.12 89.08,9.03 88.95,9
VDD on CONDUCTIVE3: outline of 218 points within 6.95,2.75 92.12,41.46 ; 19 cut-outs
VEE_A on TOP: 76.07,55.7 76.03,55.71 76,55.73 75.62,56.1 75.58,56.15 75.55,56.28 75.55,60.35 75.58,60.48 75.67,60.57 75.8,60.6 79.15,60.6 79.22,60.57 79.25,60.5 79.25,58.35 79.22,58.23 79.12,58.13 79,58.1 78.5,58.1 78.38,58.07 78.28,57.98 78.25,57.85 78.25,55.8 78.22,55.73 78.15,55.7
VEE_A on BOTTOM: 75.9,55.95 75.78,55.98 75.68,56.08 75.65,56.2 75.65,60.4 75.68,60.52 75.78,60.62 75.9,60.65 77.85,60.65 77.97,60.62 78.07,60.52 78.1,60.4 78.1,56.2 78.07,56.08 77.97,55.98 77.85,55.95
VEE_A on CONDUCTIVE3: 29.95,60.9 29.98,60.97 30.05,61 71.65,61 71.78,60.97 71.87,60.88 71.9,60.75 71.9,57.2 72.8,56.3 73.7,57.2 73.7,59.45 73.73,59.57 73.83,59.67 73.95,59.7 74.28,59.7 75,60.07 75.15,60.96 75.23,61 93.5,61 93.62,60.97 93.72,60.88 93.75,60.75 93.75,59.75 94.78,57.28 97.25,56.25 98.75,56.25 98.88,56.22 98.97,56.12 99,56 99,47.19 98.97,47.12 98.9,47.09 83.8,47.09 83.67,47.12 83.58,47.22 83.55,47.34 83.55,50.8 83.52,50.92 83.42,51.02 83.3,51.05 81.01,51.05 80.92,51.1 80.95,52.72 79.64,53.48 71.64,53.48 70.58,53.04 70.14,51.98 70.14,51.3 70.11,51.17 70.02,51.08 69.89,51.05 68.1,51.05 67.97,51.02 67.88,50.92 67.85,50.8 67.85,47.34 67.82,47.22 67.72,47.12 67.6,47.09 46.94,47.09 40.11,48.45 34.32,52.31 31.71,55.63 29.95,59.47 29.95,59.5 ; 6 cut-outs
VEE_B on TOP: 9.1,2.05 8.97,2.08 8.88,2.17 8.85,2.3 8.85,3.51 8.86,3.56 9.03,3.72 9.07,3.9 9.07,4.9 9.07,4.94 9.07,4.98 9.09,5.06 9.16,5.1 11,5.1 11.07,5.07 11.1,5 11.1,4.7 11.13,4.58 11.22,4.48 11.35,4.45 14.88,4.45 14.94,4.43 15.07,4.29 15.2,4.25 18.85,4.25 18.92,4.22 18.95,4.15 18.95,2.3 18.92,2.17 18.82,2.08 18.7,2.05
VEE_B on BOTTOM: 8.75,2.3 8.62,2.33 8.53,2.42 8.5,2.55 8.5,4 8.53,4.07 8.6,4.1 13.2,4.1 13.32,4.13 13.42,4.22 13.45,4.35 13.45,6.4 13.48,6.53 13.57,6.62 13.7,6.65 15.29,6.65 15.35,6.63 15.64,6.23 16.05,6.1 18.2,6.1 18.32,6.07 18.42,5.97 18.45,5.85 18.45,2.4 18.42,2.33 18.35,2.3
VEE_B on CONDUCTIVE3: 19.05,8.52 19.16,8.52 20,8.72 20.6,9.35 20.64,9.39 20.69,9.4 24.36,9.4 24.44,9.37 24.67,8.56 25.35,8.25 27.55,8.25 27.59,8.24 27.63,8.21 28.14,7.88 28.74,7.94 28.76,7.95 28.79,7.95 29.35,7.95 30.03,8.26 30.24,8.98 30.24,9.02 30.03,9.74 29.35,10.05 25.14,10.05 25.06,10.08 24.83,10.89 24.15,11.2 23.25,11.2 23.12,11.23 23.03,11.32 23,11.45 23,14.65 23.03,14.78 23.12,14.87 23.25,14.9 42.9,14.9 54.19,11.06 60.79,1.13 60.77,1.04 60.69,1 6.49,1 6.36,1.03 6.27,1.12 6.24,1.25 6.24,1.95 6.24,1.96 5.33,4.62 2.75,5.75 1.25,5.75 1.12,5.78 1.03,5.88 1,6 1,14.8 1.03,14.87 1.1,14.9 7.05,14.9 7.17,14.87 7.27,14.78 7.3,14.65 7.3,10.9 9.86,10.9 9.95,10.85 9.95,10.75 9.95,9.29 11.2,8.52 11.27,8.49 11.3,8.42 11.3,7.65 11.56,7.01 12.2,6.75 13.2,6.75 13.84,7.01 14.1,7.65 14.1,8.42 14.13,8.49 14.2,8.52 ; 7 cut-outs
SIG00015 on BOTTOM: 92.6,29.46 92.47,29.49 92.38,29.58 92.35,29.71 92.35,33.91 92.35,33.95 92.38,34.02 92.45,34.05 93.41,34.05 93.53,34.02 93.63,33.92 93.66,33.8 93.66,31.55 94.1,31.11 94.14,31.05 94.18,30.93 94.18,29.71 94.14,29.58 94.05,29.49 93.93,29.46
SIG00017 on BOTTOM: 90.38,29.46 90.25,29.49 90.16,29.58 90.13,29.71 90.13,30.77 90.14,30.84 90.2,30.95 90.55,31.3 90.55,33.8 90.62,33.98 90.8,34.05 91.85,34.05 91.94,34.03 92.02,33.99 92.04,33.95 92.05,33.91 92.05,29.71 92.02,29.58 91.92,29.49 91.8,29.46
SIG00042 on TOP: 69.44,51.25 69.4,51.26 69.37,51.28 69.03,51.62 69.01,51.65 69,51.69 69,54.65 69.01,54.71 69.07,54.82 69.43,55.18 69.49,55.29 69.5,55.35 69.5,57.64 69.52,57.7 69.57,57.74 69.61,57.75 69.65,57.75 70.51,57.75 70.55,57.74 70.58,57.72 70.93,57.37 71.04,57.31 71.1,57.3 71.95,57.3 72.02,57.27 72.05,57.2 72.05,56.7 72.08,56.58 72.12,56.53 72.53,56.12 72.57,56.07 72.6,55.95 72.6,53.62 72.59,53.58 72.57,53.55 72.33,53.31 72.3,53.29 72.26,53.28 71.64,53.28 70.53,52.66 70.47,51.3 70.39,51.25
SIG00043 on TOP: 69.55,58.3 69.42,58.33 69.33,58.42 69.3,58.55 69.3,59.75 69.33,59.88 69.42,59.97 69.55,60 71.8,60 71.92,59.97 72.02,59.88 72.05,59.75 72.05,58.4 72.02,58.33 71.95,58.3
SIG00044 on TOP: 61.49,54.1 61.45,54.11 61.42,54.13 60.07,55.48 60.03,55.53 60,55.65 60,57.68 60.04,57.76 61.07,57.87 61.51,58.7 61.51,58.79 61.54,58.86 61.61,58.89 61.95,58.89 62.03,58.85 62.05,58.78 63.01,57.7 64.05,58.7 64.05,59.05 64.08,59.12 64.15,59.15 64.7,59.15 65.32,59.77 65.35,59.79 65.39,59.8 68.45,59.8 68.63,59.73 68.7,59.55 68.7,55.9 68.69,55.84 68.63,55.73 67.03,54.13 67,54.11 66.96,54.1
SIG00044 on BOTTOM: 59.95,53.6 59.88,53.63 59.85,53.7 59.85,57.56 59.86,57.6 59.88,57.63 59.96,57.68 60.05,57.7 60.51,57.7 61.22,57.99 61.51,58.7 61.51,58.9 61.54,59.02 61.63,59.12 61.76,59.15 62.01,59.15 62.09,59.11 62.1,59.02 63.05,57.7 64,59.02 64.01,59.11 64.09,59.15 64.45,59.15 64.51,59.14 64.62,59.08 64.78,58.92 64.82,58.87 64.85,58.75 64.85,54.25 64.84,54.19 64.78,54.08 64.37,53.67 64.32,53.63 64.2,53.6
SIG00050 on TOP: 80.91,51.3 80.83,51.35 80.82,51.44 80.68,52.76 79.45,53.27 79.44,53.27 78.95,53.27 78.88,53.29 78.85,53.37 78.85,54.91 78.86,54.95 78.88,54.98 79.27,55.37 79.3,55.39 79.34,55.4 81,55.4 81.12,55.43 81.22,55.52 81.25,55.65 81.25,57.75 81.28,57.88 81.38,57.97 81.5,58 84.95,58 85.13,57.93 85.2,57.75 85.2,52.25 85.19,52.19 85.13,52.08 84.38,51.33 84.35,51.31 84.31,51.3
SIG00051 on TOP: 80.15,58.75 80.03,58.78 79.93,58.88 79.9,59 79.9,59.7 79.94,59.84 80.06,59.93 80.1,59.94 80.36,59.9 80.59,59.94 80.63,59.95 84.3,59.95 84.42,59.92 84.52,59.83 84.55,59.7 84.55,59.1 84.52,59.03 84.45,59 84.05,59 83.93,58.97 83.88,58.93 83.73,58.78 83.7,58.76 83.66,58.75
SIG00057 on BOTTOM: 69.39,29.4 69.35,29.41 69.32,29.43 68.07,30.68 68.03,30.73 68,30.85 68,35.55 68.01,35.61 68.07,35.72 68.22,35.87 68.25,35.89 68.29,35.9 69.11,35.9 69.18,35.87 69.21,35.8 69.21,35.35 69.21,35.34 69.53,34.33 70.5,33.9 73.8,33.9 73.87,33.87 73.9,33.8 73.9,33.29 73.89,33.25 73.87,33.22 72.7,32.05 72.7,31.29 72.69,31.25 72.67,31.22 72.28,30.83 72.25,30.81 72.21,30.8 71.85,30.8 71.67,30.73 71.6,30.55 71.6,29.5 71.57,29.43 71.5,29.4
SIG00057_502750 on TOP: 17.14,28.1 17.1,28.11 17.07,28.13 16.93,28.27 16.91,28.3 16.9,28.34 16.9,30.89 16.92,31 16.93,31.08 16.93,31.4 16.96,31.47 17.03,31.5 18.29,31.5 18.41,31.53 18.47,31.57 19.17,32.28 19.2,32.3 19.24,32.31 19.96,32.31 20,32.3 20.03,32.28 20.53,31.77 20.65,31.71 20.71,31.7 21.95,31.7 21.99,31.7 22.4,31.7 22.52,31.67 22.62,31.58 22.65,31.45 22.65,28.35 22.62,28.23 22.52,28.13 22.4,28.1
SIG00063 on BOTTOM: 19.35,4.7 19.28,4.73 19.25,4.8 19.25,6.4 19.22,6.52 19.18,6.57 18.72,7.03 18.63,7.19 18.54,7.3 18.52,7.33 18.52,7.37 18.52,8.65 18.54,8.72 18.61,8.75 18.99,8.75 19.01,8.74 20.09,9.02 20.56,10.02 20.56,10.75 20.59,10.82 20.66,10.85 21.36,10.85 21.4,10.84 21.43,10.82 21.67,10.58 21.69,10.55 21.7,10.51 21.7,4.95 21.67,4.83 21.57,4.73 21.45,4.7
SIG00065 on BOTTOM: 22.7,2.6 22.61,2.62 22.53,2.66 22.51,2.7 22.5,2.74 22.5,3.75 22.49,3.86 22.45,4 22.45,7.2 22.52,7.38 22.7,7.45 24.4,7.45 24.47,7.42 24.5,7.35 24.5,7.05 24.53,6.93 24.57,6.88 25.2,6.25 28.75,6.25 28.97,6.47 29,6.49 29.04,6.5 35.16,6.5 35.2,6.49 35.23,6.47 36.13,5.57 36.17,5.52 36.2,5.4 36.2,4.5 36.17,4.38 36.08,4.28 35.95,4.25 35.69,4.25 34.98,3.96 34.69,3.25 34.69,3 34.66,2.88 34.56,2.78 34.44,2.75 34.4,2.75 34.27,2.78 34.18,2.88 34.15,3 34.15,3.25 33.22,4.25 32.16,3.39 32.16,2.85 32.13,2.73 32.03,2.63 31.91,2.6
